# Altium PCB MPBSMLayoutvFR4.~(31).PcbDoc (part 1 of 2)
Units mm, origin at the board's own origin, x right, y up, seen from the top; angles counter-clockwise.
Board outline 131.7 x 110.39 mm, 4 copper layers (Top Layer, Power, GroundPlane, Bottom Layer), stack 2.286 mm thick; 158 components, 77 nets, 439 pads, 119 vias.
Unrouted connection lines stored in the file: 14.
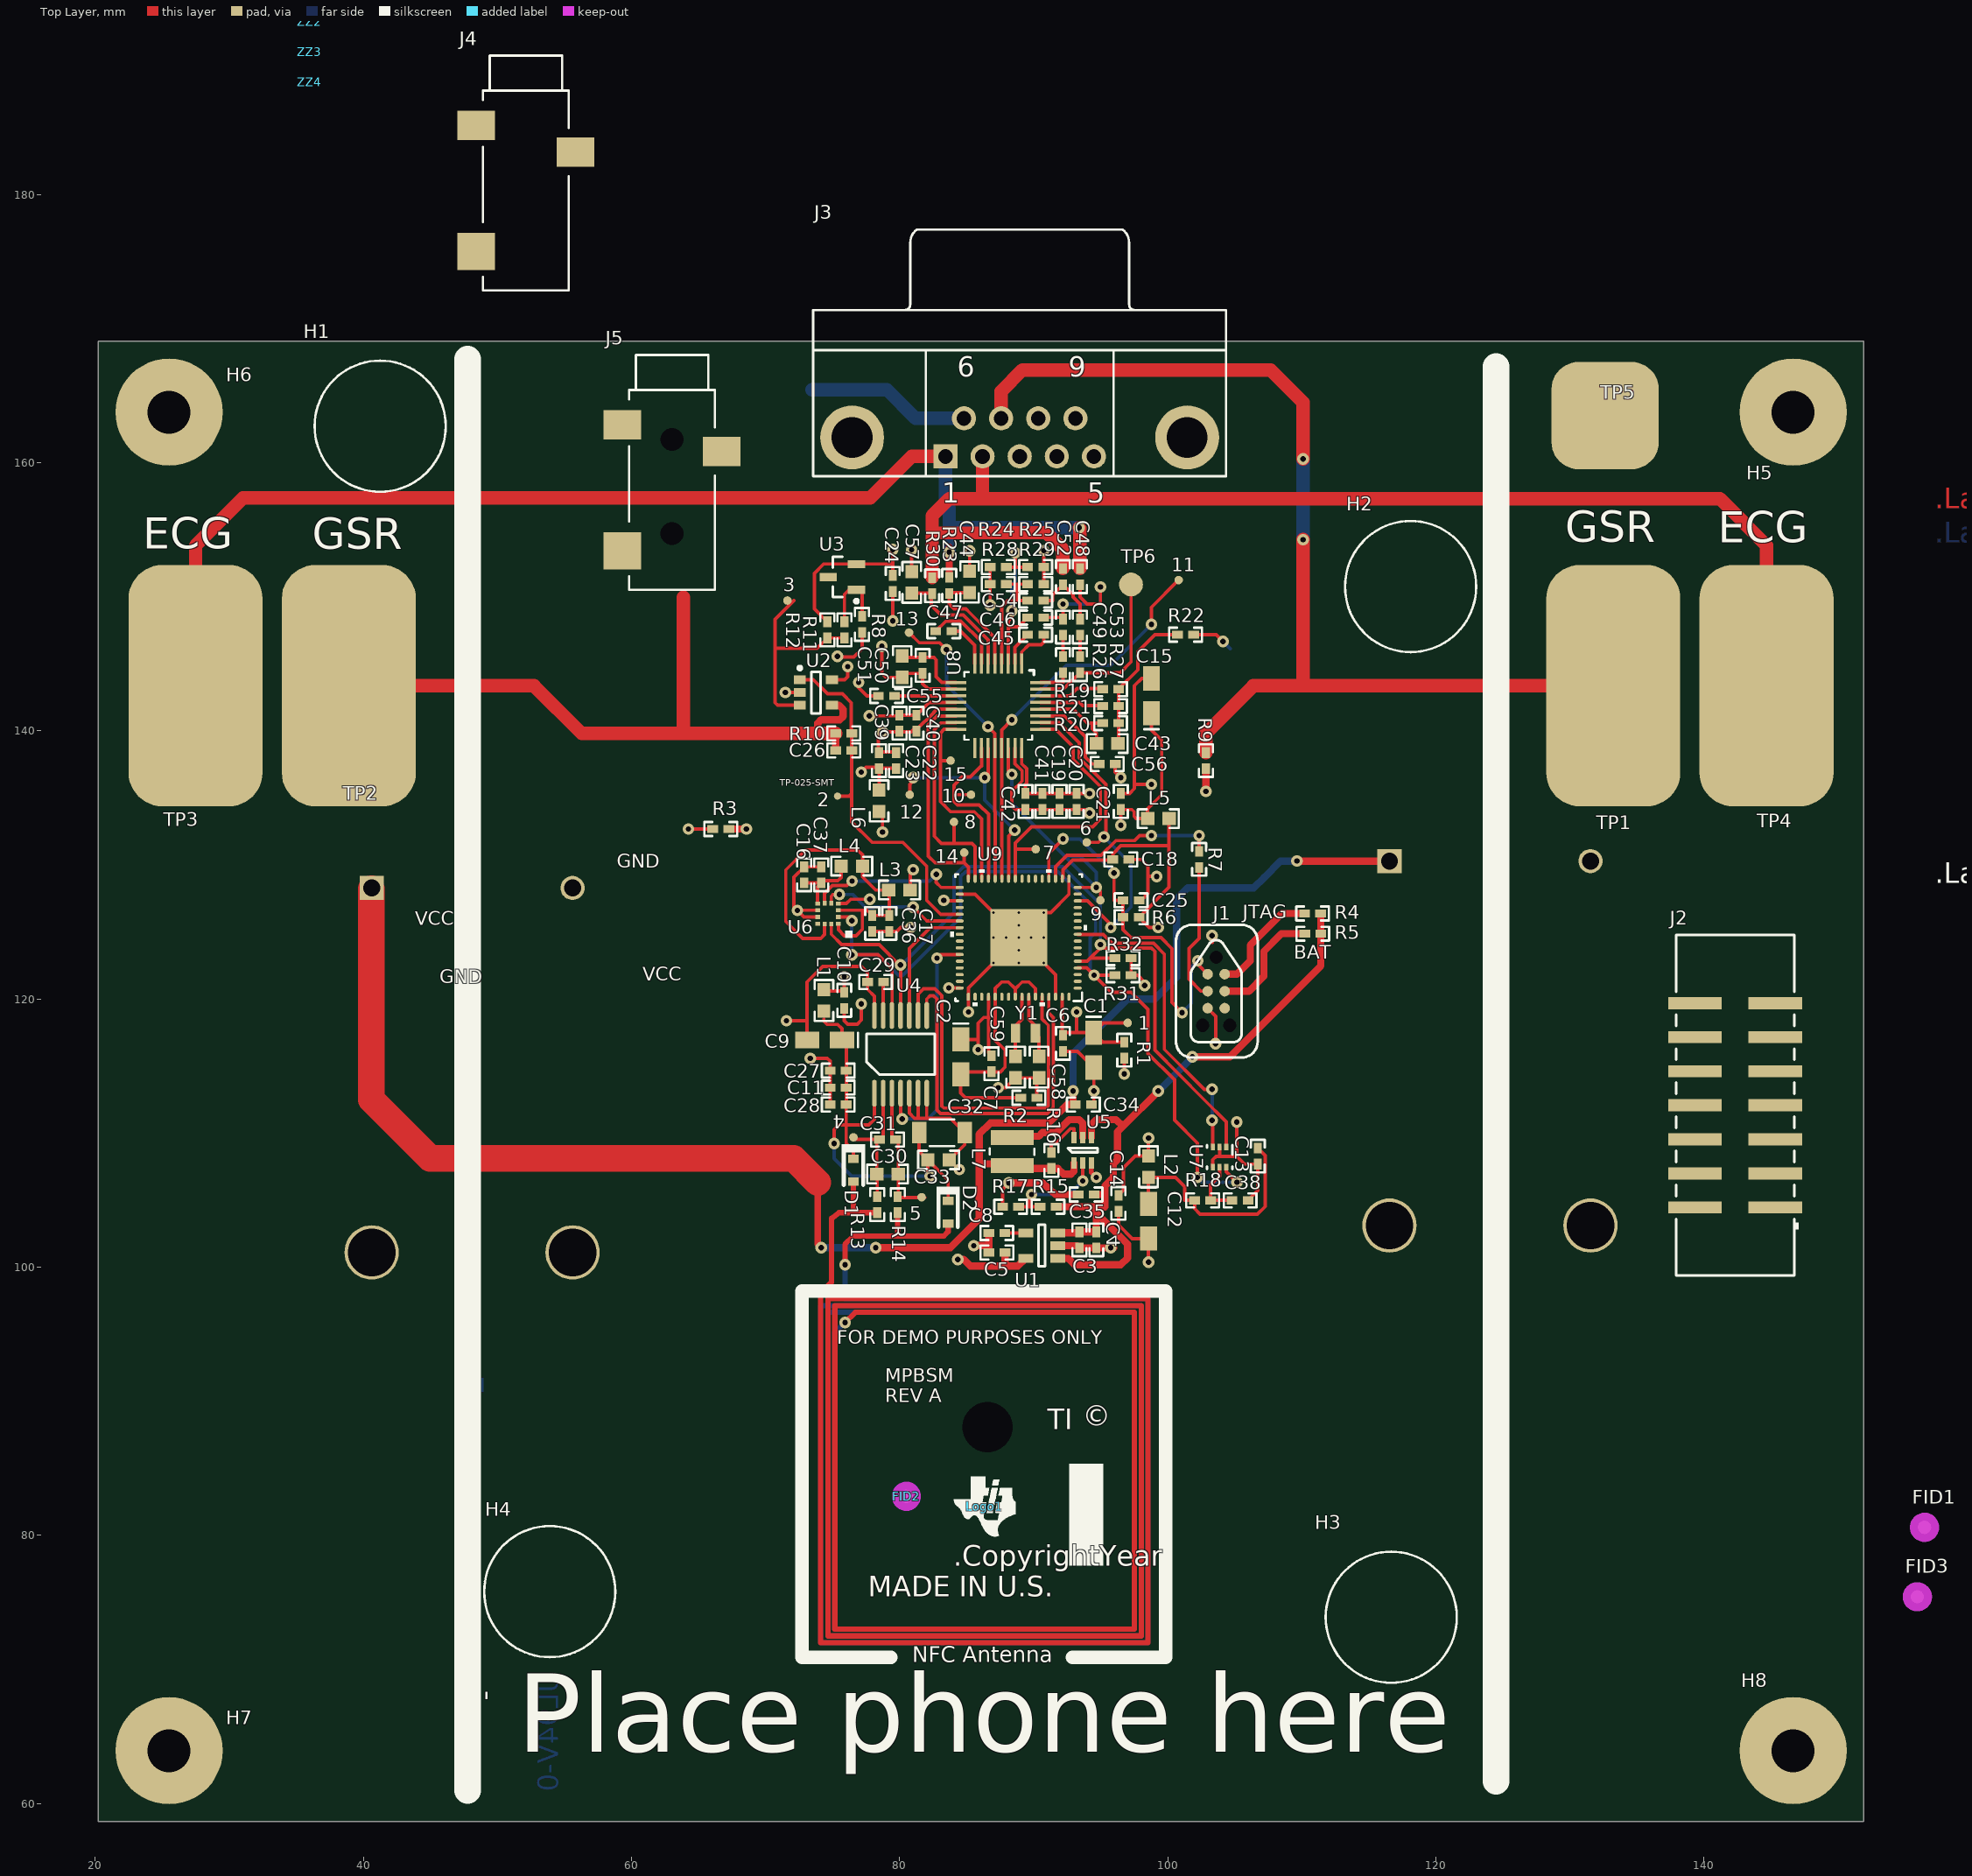
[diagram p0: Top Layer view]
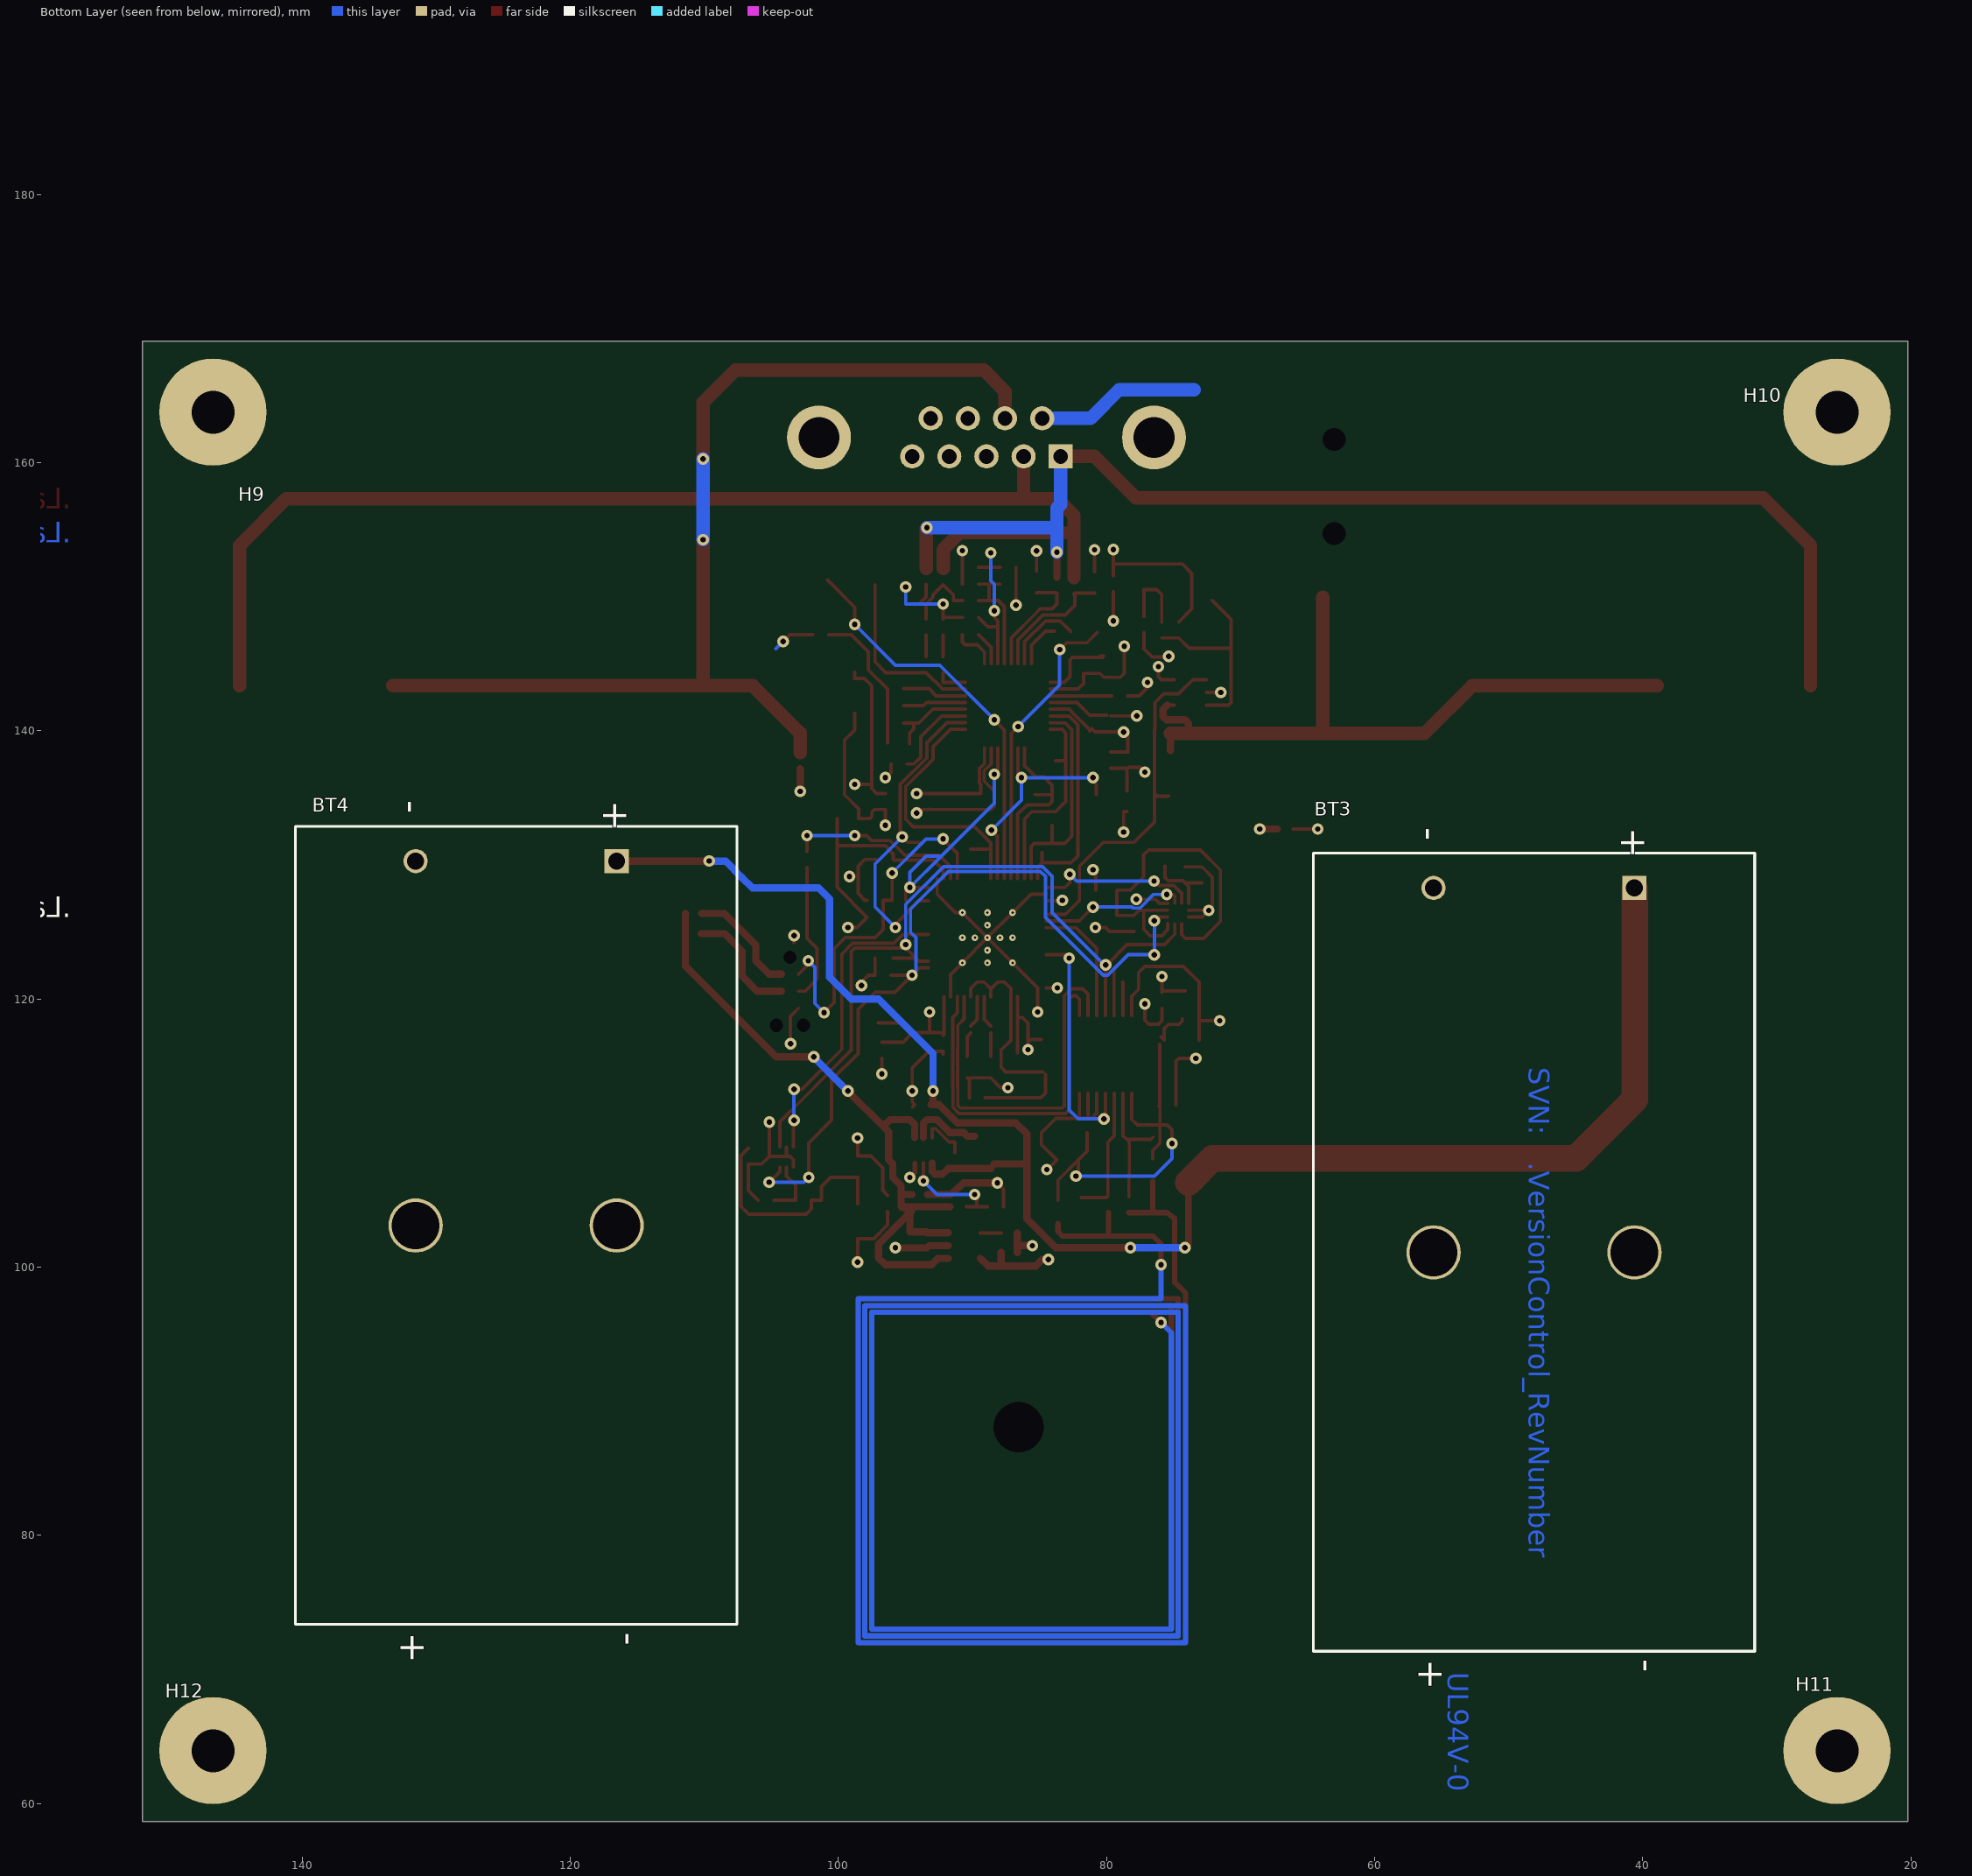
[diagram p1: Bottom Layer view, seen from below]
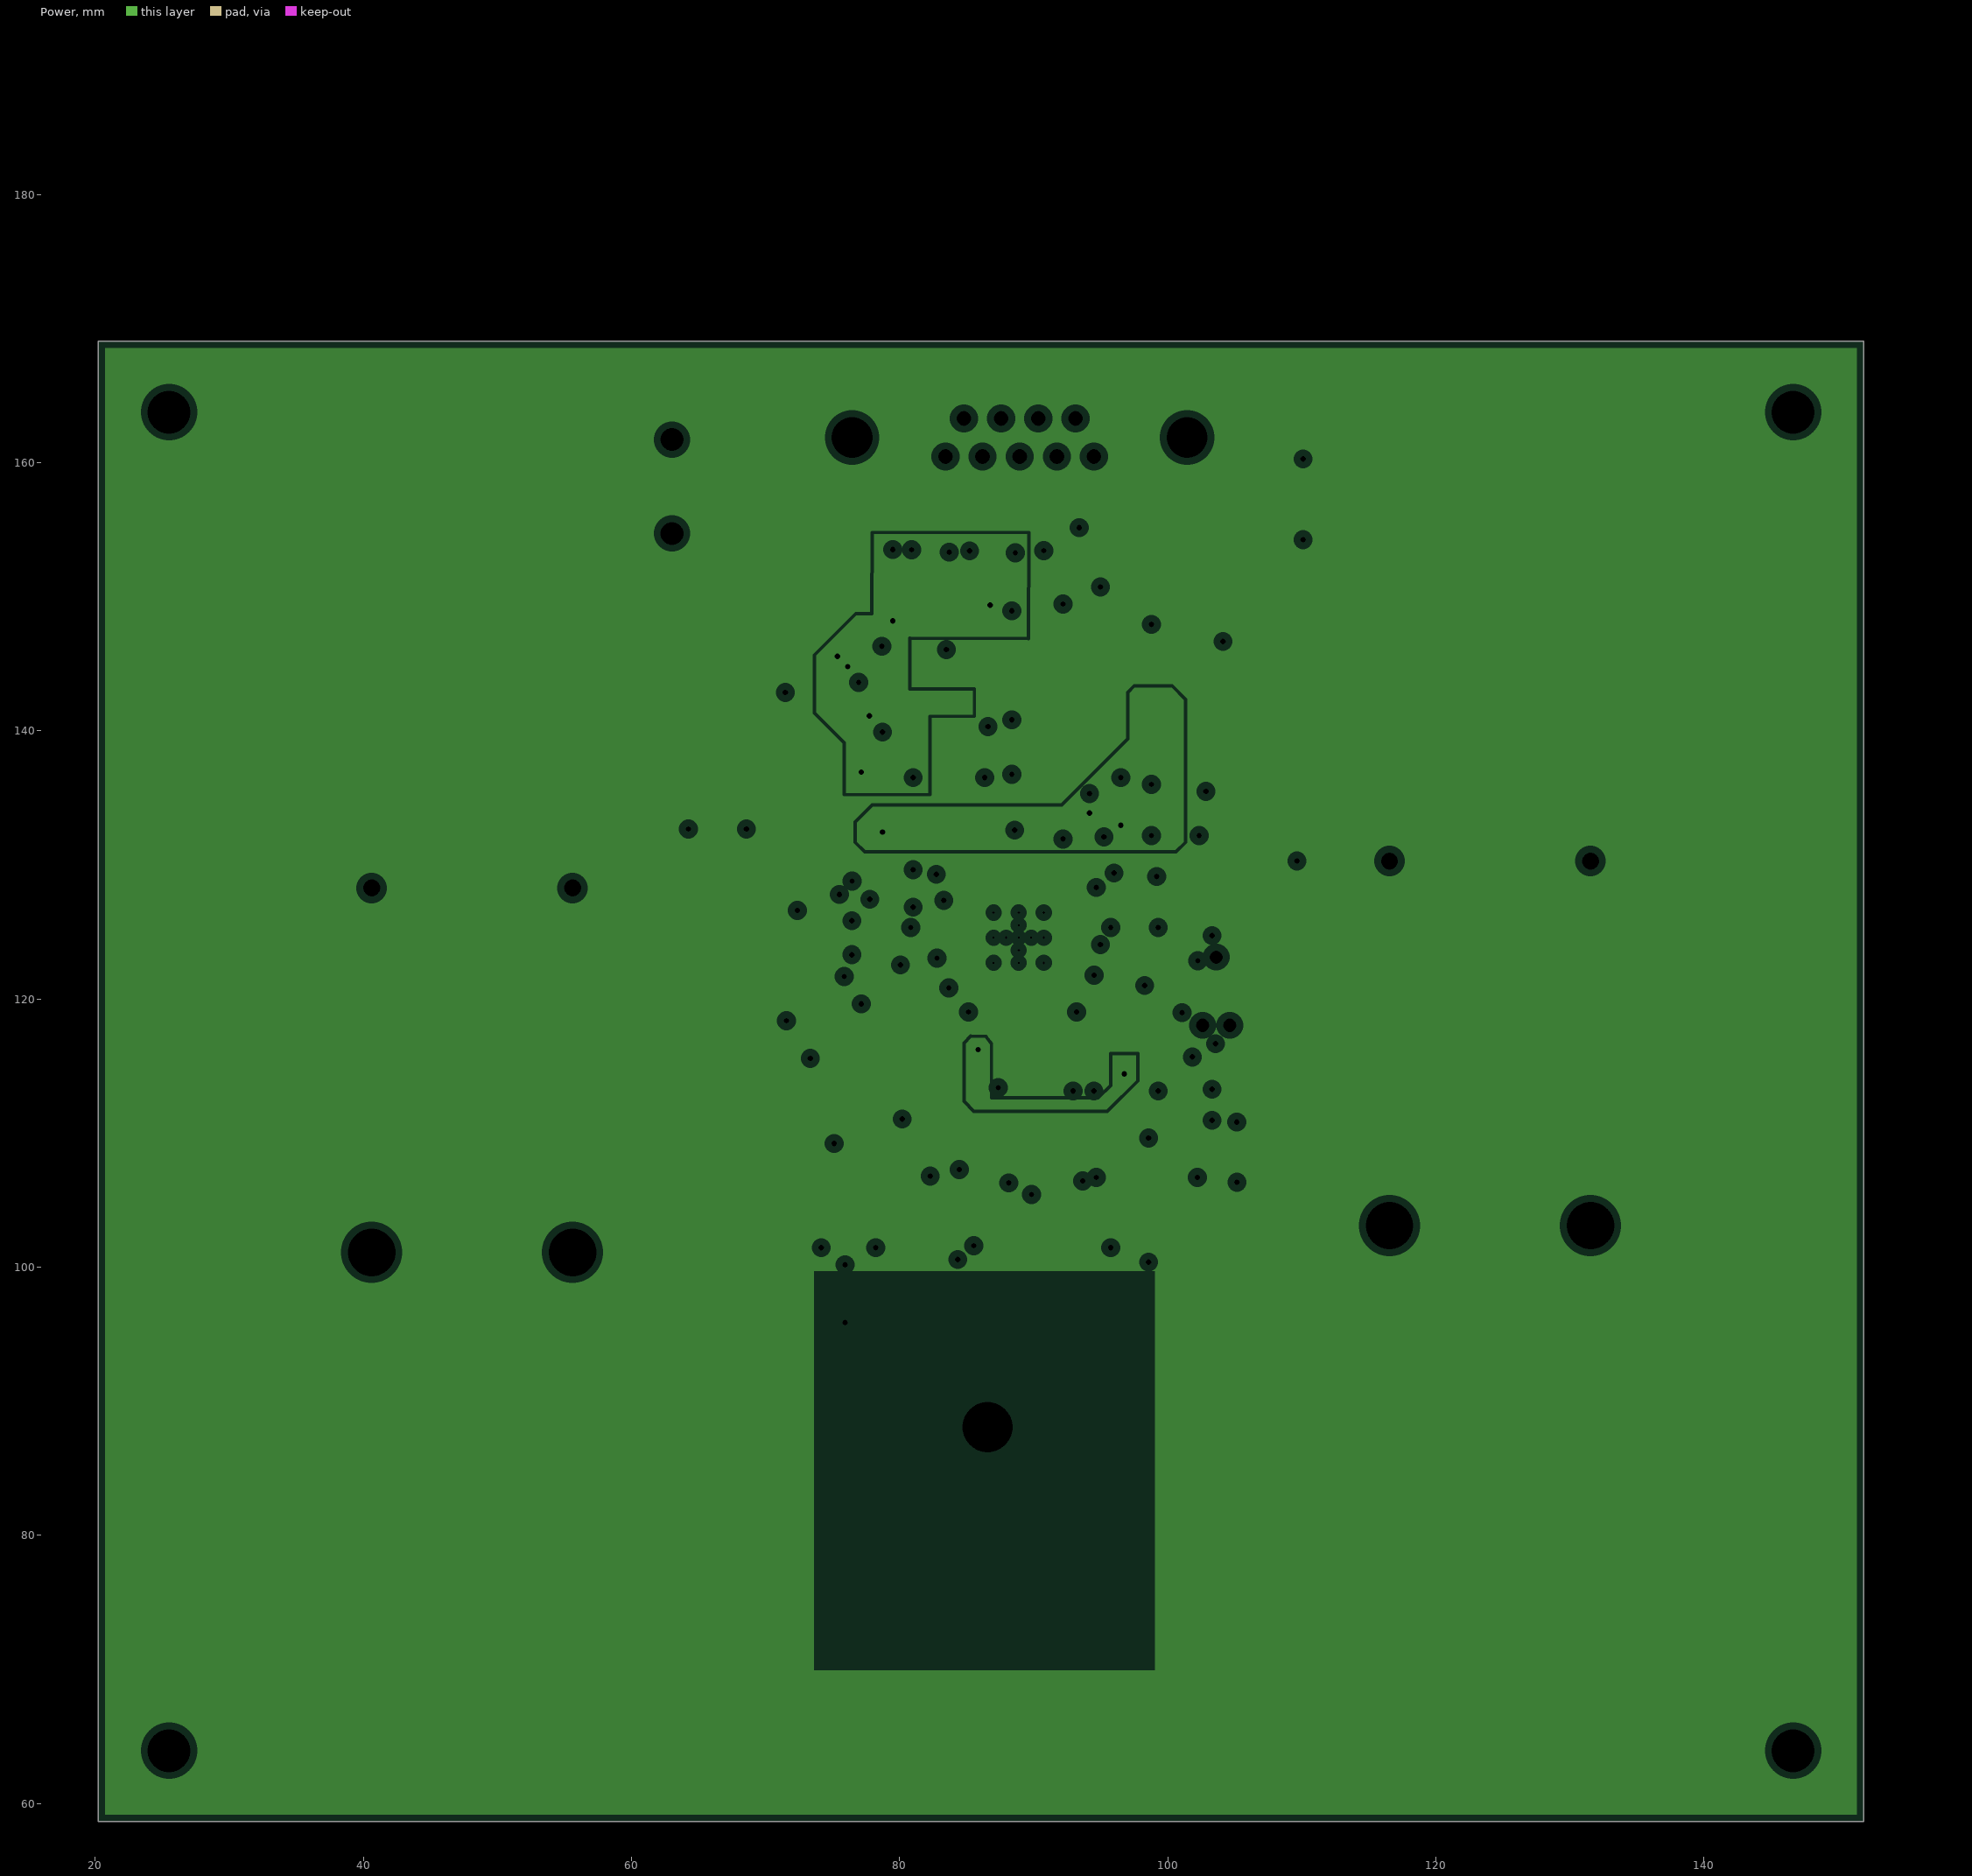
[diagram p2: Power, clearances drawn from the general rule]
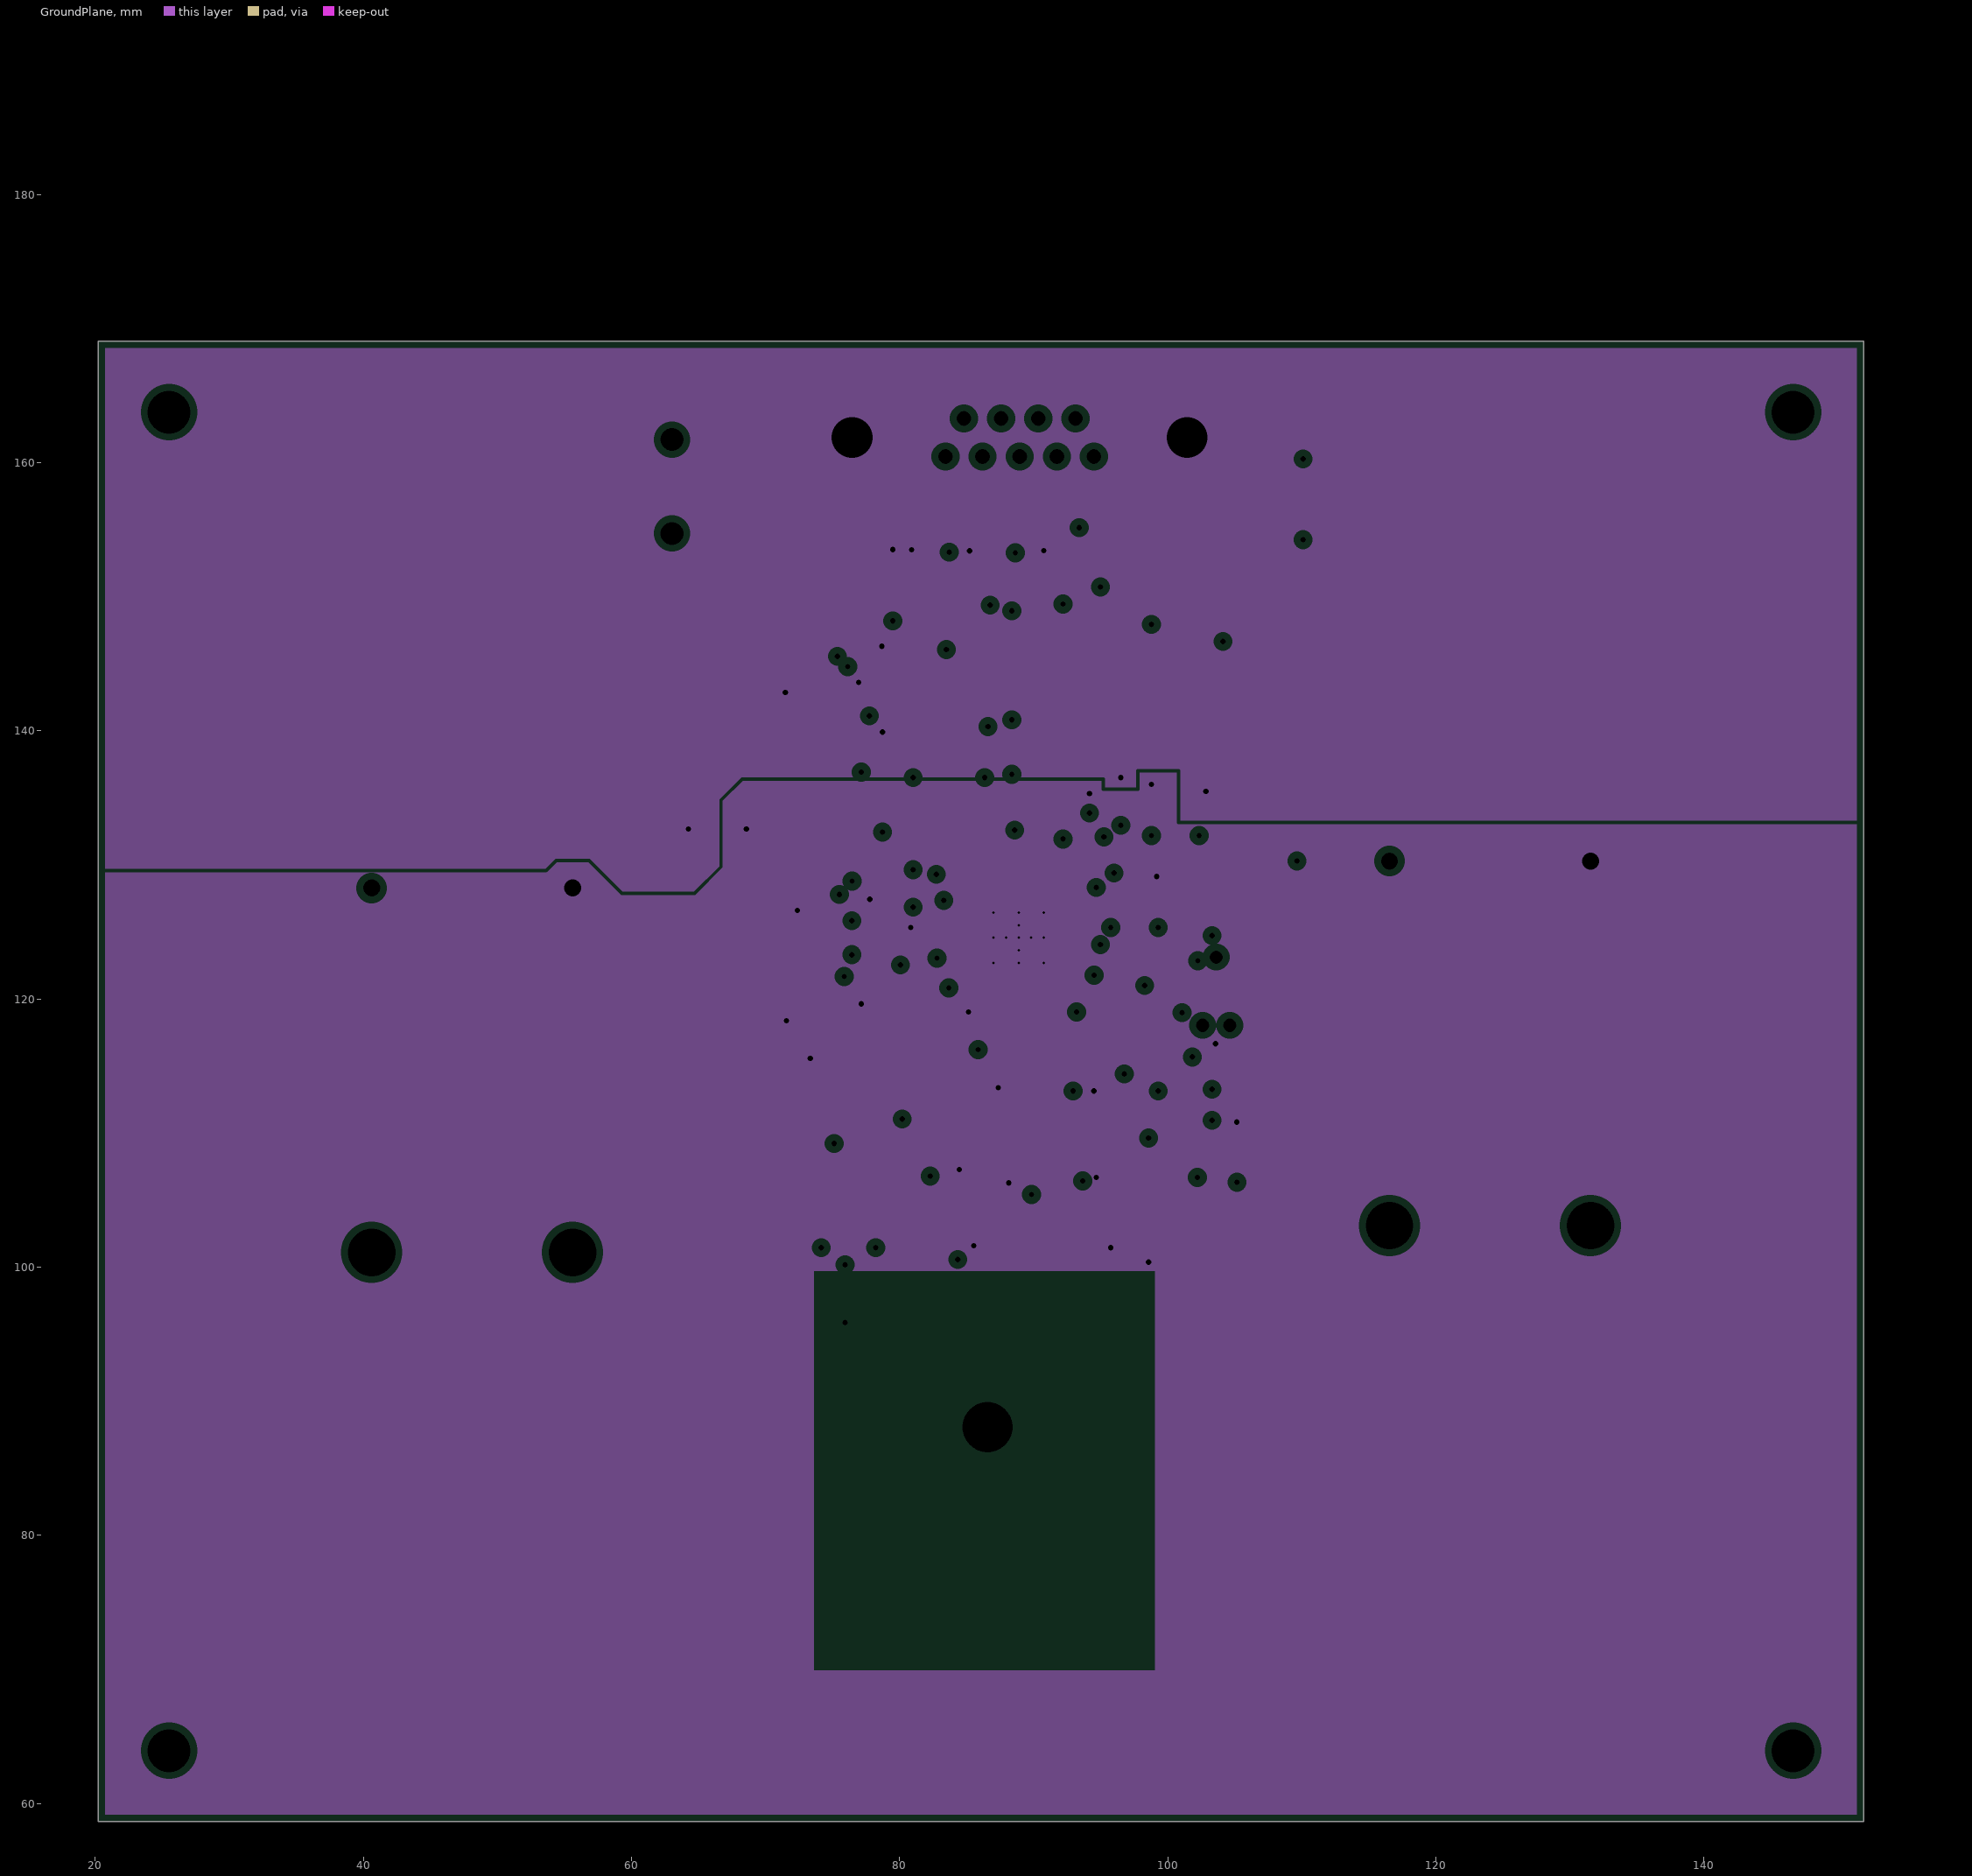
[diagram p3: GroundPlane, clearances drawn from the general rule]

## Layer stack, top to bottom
Top Solder: solder mask 0.0102, Solder Resist, Dk 3.5
Top Layer: signal copper 0.0356
Dielectric1: core 1.5037, FR-4, Dk 4.8
Power: plane copper 0.0356, net (Multiple Nets)
Dielectric2: prepreg 0.32, FR-4, Dk 4.8
GroundPlane: plane copper 0.0356, net (Multiple Nets)
Dielectric3: core 0.32, FR-4, Dk 4.8
Bottom Layer: signal copper 0.0356
Bottom Solder: solder mask 0.0102, Solder Resist, Dk 3.5

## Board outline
20.218,169.037 20.218,58.649 150.825,58.649 151.917,58.649 151.917,158.471 151.917,169.037 20.218,169.037

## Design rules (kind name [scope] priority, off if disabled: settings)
AcuteAngle [All] p1: minimum=4.50000000000000E+0001 checktracksonly=FALSE
AssemblyTestPointUsage [All] p1: valid=2
Clearance Clearance_BoardEdge_MountingHoles [OnCopper and InComponentClass('Mounting Holes') vs IsKeepOut] p1: gap=1.016
Clearance Clearance_BoardEdge_Poly [OnCopper and InPoly vs IsKeepOut] p2: gap=0.635
Clearance Clearance_BoardEdge [OnCopper and Not InComponentClass('Logo') and not InComponentClass('FiducialMark') and not InRegion(1000,500,4000,800) and Not IsKeepout vs IsKeepOut] p3: gap=1.905
Clearance Clearance_Poly [InPolygon] p4: gap=0.635
Clearance [All] p5: gap=0.1
ComponentClearance ComponentClearance_Shunt [InComponentClass('Header') vs InComponentClass('Shunt')] p1: gap=0 collisioncheckmode=3 verticalgap=0 showdistances=FALSE
ComponentClearance ComponentClearance_MountingHoles_FiducialMarks [InComponentClass('Mounting Holes') vs InComponentClass('FiducialMark')] p2: gap=1.27 collisioncheckmode=3 verticalgap=0.254 showdistances=FALSE
ComponentClearance ComponentClearance_Logo [InComponentClass('Logo')] p3: gap=1.27 collisioncheckmode=3 verticalgap=0.254 showdistances=FALSE
ComponentClearance ComponentClearance_ScrewToNut [(HasFootprint('NY PMS 440 0025 PH')) vs (HasFootprint('Keystone_1902C'))] p4: gap=0.127 collisioncheckmode=3 verticalgap=0.254 showdistances=FALSE
ComponentClearance ComponentClearance_MountingHoles [InComponentClass('Mounting Holes')] p5: gap=6.35 collisioncheckmode=3 verticalgap=2540 showdistances=FALSE
ComponentClearance ComponentClearance_SmallPassives [HasFootprint('0201*') or HasFootprint('0402*') or HasFootprint('0508') or HasFootprint('0603*') or HasFootprint('0612') or HasFootprint('0805*') or HasFootprint('0815*') or HasFootprint('0830*') or HasFootprint('1206*') or HasFootprint('1210*') or HasFootprint('1808*') or HasFootprint('1812*') or HasFootprint('1825*') or HasFootprint('2010*') or HasFootprint('2220*') or HasFootprint('2225*') or HasFootprint('2512*') or HasFootprint('2728*') or HasFootprint('3518*') vs HasFootprint('0201*') or HasFootprint('0402*') or HasFootprint('0508') or HasFootprint('0603*') or HasFootprint('0612') or HasFootprint('0805*') or HasFootprint('0815*') or HasFootprint('0830*') or HasFootprint('1206*') or HasFootprint('1210*') or HasFootprint('1808*') or HasFootprint('1812*') or HasFootprint('1825*') or HasFootprint('2010*') or HasFootprint('2220*') or HasFootprint('2225*') or HasFootprint('2512*') or HasFootprint('2728*') or HasFootprint('3518*')] p6: gap=0.508 collisioncheckmode=3 verticalgap=0.254 showdistances=FALSE
ComponentClearance ComponentClearance_THtoSMT [IsThruComponent vs IsSMTComponent] p7: gap=2.54 collisioncheckmode=3 verticalgap=0.762 showdistances=FALSE
ComponentClearance ComponentClearance_THtoTH [IsThruComponent vs IsThruComponent] p8: gap=3 collisioncheckmode=3 verticalgap=0.762 showdistances=FALSE
ComponentClearance [All] p9: gap=1.016 collisioncheckmode=3 verticalgap=0.254 showdistances=FALSE
DiffPairsRouting [All] p1: maxlimit=2.54 minlimit=0.254 mostfreqgap=0.254 toplayer_minwidth=0.381 toplayer_maxwidth=0.381 toplayer_prefwidth=0.381 bottomlayer_minwidth=0.381 bottomlayer_maxwidth=0.381 bottomlayer_prefwidth=0.381 maxuncoupledlength=25.4
FabricationTestPointUsage TestPointUsage [All] p1: valid=2 allowmultiple=FALSE
FabricationTestpoint Testpoint [All] p1: side=3 testpointundercomponent=TRUE minsize=1.016 maxsize=2.54 preferedsize=1.524 minholesize=0 maxholesize=1.016 preferedholesize=0.813 testpointgrid=0.025 allowsidetop=TRUE allowsidebottom=TRUE usegrid=TRUE gridtolerance=0
FanoutControl Fanout_LCC [IsLCC] p1: bgadir=Out bgaviamode=Centered fanoutstyle=Auto fanoutdirection=Alternating viagrid=0.025 // Fanout_LCC (Default Rule)
FanoutControl Fanout_BGA [IsBGA] p2: bgadir=Out bgaviamode=Centered fanoutstyle=Auto fanoutdirection=Alternating viagrid=0.025 // Fanout_BGA (Default Rule)
FanoutControl Fanout_Default [All] p4: bgadir=Out bgaviamode=Centered fanoutstyle=Auto fanoutdirection=Alternating viagrid=0.025 // Fanout_Default (Default Rule)
FanoutControl Fanout_Small [(CompPinCount < 5)] p5: bgadir=Out bgaviamode=Centered fanoutstyle=Auto fanoutdirection=OutThenIn viagrid=0.025 // Fanout_Small (Default Rule)
Height [All] p1: minheight=0 maxheight=55.4 prefheight=12.7
HoleSize [All] p1: absolutevalues=TRUE maxlimit=6.375 minlimit=0.1 maxpercent=80.000 minpercent=20.000
MinimumAnnularRing MinimumAnnularRing_ThermalPadVias [IsVia and InAnyComponent] p1: minimumring=0.15
MinimumAnnularRing [All] p2: minimumring=0.229
MinimumSolderMaskSliver MinimumSolderMaskSliver_Logo [InComponentClass('Logo') vs InComponentClass('Logo')] p1: minsoldermaskwidth=0.018
MinimumSolderMaskSliver [All] p2: minsoldermaskwidth=0.08
PlaneClearance [All] p1: clearance=0.508
PlaneConnect [All] p1: planeconnectstyle=Relief reliefexpansion=0.254 reliefentries=4 reliefconductorwidth=0.254 reliefairgap=0.254
PolygonConnect [All] p1: connectstyle=Relief reliefconductorwidth=0.254 reliefentries=4 polygonreliefangle="90 Angle" airgapwidth=0.254
RoutingVias ThermalPadVias [IsVia and InAnyComponent] p1: holewidth=0.2 width=0.5 viastyle="Through Hole" minholewidth=0.2 minwidth=0.5 maxholewidth=0.33 maxwidth=0.6
RoutingVias [All] p2: holewidth=0.406 width=0.864 viastyle="Through Hole" minholewidth=0.2 minwidth=0.66 maxholewidth=1.016 maxwidth=1.651
SMDToCorner [All] p1: distance=30000
SilkToSilkClearance SilkToSilkClearance_Pb-FreeLogo [(HasFootprint('Pb-Free_Overlay_Medium') OR HasFootprint('Pb-Free_Overlay_Small')) vs (HasFootprint('Pb-Free_Overlay_Medium') OR HasFootprint('Pb-Free_Overlay_Small'))] p1: silktosilkclearance=0
SilkToSilkClearance [All] p2: silktosilkclearance=0
SilkToSolderMaskClearance SilkscreenOverComponentPads [IsPad] p1: minsilkscreentomaskgap=0.127 clearancetoexposedcopper=TRUE
SolderMaskExpansion [All] p1: expansion=0.05
Width [All] p1: maxlimit=2.54 minlimit=0.152 preferedwidth=0.254 checkconnectedcopper=TRUE
14 further rules are at their usual default settings.

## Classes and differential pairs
component class "Mounting Holes": H5 H6 H7 H8
component class "Analog Connector": J3
component class Transponder: 4 5 C27 C28 C29 C30 C31 C32 C33 D1 D2 R13 R14 U4
component class Temperature: C38 R18 U7
component class "Power Filtering": 1 C1 C2 C3 C4 C5 C6 C7 C8 C9 C10 C11 C12 C13 C14 C15 C16 C17 C18 C19 C20 C21 C22 C23 C24 L1 L2 L3 L4 L5 L6 R1 R2 R3 U1
component class MSP430FR5XXX: C58 C59 R31 R32 U9 Y1
component class "JTAG SPY-BY-WIRE": C25 J1 J2 R4 R5 R6 R7
component class GSR: 2 3 C26 R8 R9 R10 R11 R12 U2 U3
component class ECG: 6 7 8 9 10 11 12 13 14 15 C39 C40 C41 C42 C43 C44 C45 C46 C47 C48 C49 C50 C51 C52 C53 C54 C55 C56 C57 R19 R20 R21 R22 R23 R24 R25 R26 R27 R28 R29 R30 TP6 U8
component class "Boost Converter": C34 C35 L7 R15 R16 R17 U5
component class BMA280: C36 C37 U6
component class Battery: BT3 BT4 U?
component class AssemblyNote: ZZ1 ZZ2 ZZ3 ZZ4
component class FiducialMark: FID1 FID2 FID3
component class Designator: FID1 FID2 FID3 H1 H2 H3 H4 H5 H6 H7 H8 H9 H10 H11 H12 Logo1 ZZ1 ZZ2 ZZ3 ZZ4
component class Logo: Logo1

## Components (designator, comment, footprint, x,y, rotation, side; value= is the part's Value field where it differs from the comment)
1 "TP-025-SMT" TP_25MIL-SMT#1 97.003,118.212 r90 top
2 "TP-025-SMT" TP_25MIL-SMT#2 75.362,135.128 r0 top
3 "TP-025-SMT" TP_25MIL-SMT#1 71.628,149.708 r0 top
4 "TP-025-SMT" TP_25MIL-SMT#1 76.551,109.676 r0 top
5 "TP-025-SMT" TP_25MIL-SMT#1 81.636,105.207 r270 top
6 "TP-025-SMT" TP_25MIL-SMT#1 93.955,131.674 r0 top
7 "TP-025-SMT" TP_25MIL-SMT#1 90.145,131.166 r0 top
8 "TP-025-SMT" TP_25MIL-SMT#1 84.049,133.198 r0 top
9 "TP-025-SMT" TP_25MIL-SMT#1 94.971,127.356 r0 top
10 "TP-025-SMT" TP_25MIL-SMT#1 85.319,135.23 r0 top
11 "TP-025-SMT" TP_25MIL-SMT#1 100.813,151.232 r0 top
12 "TP-025-SMT" TP_25MIL-SMT#1 80.747,135.23 r0 top
13 "TP-025-SMT" TP_25MIL-SMT#1 80.696,147.32 r0 top
14 "TP-025-SMT" TP_25MIL-SMT#1 84.811,130.912 r90 top
15 "TP-025-SMT" TP_25MIL-SMT#1 83.795,137.77 r0 top
BT3 "2462" Keystone_2462 48.108,114.681 r270 bottom
BT4 "2462" Keystone_2462 124.028,116.688 r270 bottom
C1 "293D106X9010A2TE3" 3216-18 94.463,116.18 r270 top
C2 "293D106X9010A2TE3" 3216-18 84.557,115.672 r270 top
C3 "C1005X5R1A104K" 0402 93.401,102.028 r270 top
C4 "C1005X5R0J105M" 0402 94.671,102.028 r270 top
C5 "C1005X5R1C225K050BC" 0402 87.254,101.092 r180 top
C6 "C1005X5R1A104K" 0402 92.177,116.688 r270 top
C7 "C1005X5R1A104K" 0402 86.843,115.164 r270 top
C8 "C1005X7R1E103K" 0402 87.249,102.54 r180 top
C9 "293D105X9016A2TE3" 3216-18 74.397,116.942 r180 top
C10 "C1005X5R1A104K" 0402 75.87,119.888 r270 top
C11 "C1005X5R1A104K" 0402 75.413,113.386 r180 top
C12 "293D106X9010A2TE3" 3216-18 98.56,103.422 r270 top
C13 "C1005X5R1A104K" 0402 106.705,108.28 r270 top
C14 "C1005X5R1A104K" 0402 96.319,104.75 r270 top
C15 "293D105X9016A2TE3" 3216-18 98.781,142.596 r90 top
C16 "CL05A106MQ5NUNC" 0402 72.873,129.247 r90 top
C17 "CL05A106MQ5NUNC" 0402 79.223,125.624 r270 top
C18 "C1005X5R1A104K" 0402 96.495,130.404 r0 top
C19 "C1005X5R1A104K" 0402 91.923,134.722 r90 top
C20 "C1005X5R1C225K050BC" 0402 93.193,134.722 r90 top
C21 "CL05A106MQ5NUNC" 0402 96.495,134.722 r90 top
C22 "CL05A106MQ5NUNC" 0402 79.731,137.77 r90 top
C23 "C1005X5R1A104K" 0402 78.461,137.77 r90 top
C24 "C1005X5R1A104K" 0402 79.477,150.978 r90 top
C25 "C1005X8R1H222K" 0402 97.257,127.356 r0 top
C26 "C1005X7R1E103K" 0402 75.829,138.532 r180 top
C27 "C1005X5R0J105M" 0402 75.413,114.656 r180 top
C28 "C1005X5R1A104K" 0402 75.413,112.116 r180 top
C29 "GRM155R60J474KE19D" 0402 78.207,121.26 r0 top
C30 "C1608C0G1H330J" 0603 79.091,106.941 r0 top
C31 "GRM1555C1H390JA01D" 0402 79.091,109.515 r0 top
C32 "C3216X5R1A107M160AC" 1206_190 83.155,110.023 r0 top
C33 "Used in BOM report" 0603 82.901,107.991 r0 top
C34 "CL05A106MQ5NUNC" 0402 93.701,112.116 r0 top
C35 "CL05A106MQ5NUNC" 0402 93.904,105.41 r180 top
C36 "C1005X5R1A104K" 0402 77.953,125.624 r270 top
C37 "C1005X5R1A104K" 0402 74.143,129.247 r90 top
C38 "C1005X7R1E103K" 0402 105.389,104.978 r0 top
C39 "C1005X5R1C105K050BC" 0402 79.985,140.564 r270 top
C40 "C1005X5R1A104K" 0402 81.255,140.564 r270 top
C41 "C1005X5R1C105K050BC" 0402 90.653,134.722 r90 top
C42 "C1005X5R1A104K" 0402 89.383,134.722 r90 top
C43 "C0603C152K5RACTU" 0603 95.479,139.04 r180 top
C44 "GRM1885C1H302JA01D" 0603 85.217,151.091 r90 top
C45 "GRM155R61A472KA01D" 0402 90.145,147.168 r0 top
C46 "C1005X8R1H222K" 0402 90.145,148.438 r0 top
C47 "GRM155R61A472KA01D" 0402 83.287,147.422 r180 top
C48 "C1005X5R1A104K" 0402 93.447,151.486 r270 top
C49 "C1005X8R1H222K" 0402 92.177,147.722 r90 top
C50 "C1005X5R1A104K" 0402 81.712,144.872 r270 top
C51 "C1608X5R0J106M" 0603 80.188,144.78 r270 top
C52 "C1005X5R1A104K" 0402 92.177,151.486 r270 top
C53 "C1005X8R1H222K" 0402 93.447,147.722 r90 top
C54 "C1005X8R1H222K" 0402 90.145,149.708 r0 top
C55 "C1005X5R1C105K050BC" 0402 79.015,142.596 r180 top
C56 "C1005X5R1C105K050BC" 0402 95.479,137.516 r0 top
C57 "GRM1885C1H302JA01D" 0603 80.895,151.063 r90 top
C58 "06035A100JAT2A" 0603 90.399,114.91 r270 top
C59 "06035A100JAT2A" 0603 88.646,114.91 r270 top
D1 "CDBU0130L" SOD-523F 76.551,107.229 r270 top
D2 "CDBU0130L" SOD-523F 83.617,104.089 r270 top
FID1 "Fiducial" Fiducial10-20 156.439,80.594 r0 top
FID2 "Fiducial" Fiducial10-20 80.493,82.906 r0 top
FID3 "Fiducial" Fiducial10-20 155.905,75.413 r0 top
H1 "SJ61A2" Bumpon_SJ61A2 41.25,162.712 r0 top
H2 "SJ61A2" Bumpon_SJ61A2 118.11,150.749 r0 top
H3 "SJ61A2" Bumpon_SJ61A2 116.662,73.889 r0 top
H4 "SJ61A2" Bumpon_SJ61A2 53.899,75.794 r0 top
H5 "NY PMS 440 0025 PH" "NY PMS 440 0025 PH" 146.634,163.754 r90 top
H6 "NY PMS 440 0025 PH" "NY PMS 440 0025 PH" 25.502,163.754 r90 top
H7 "NY PMS 440 0025 PH" "NY PMS 440 0025 PH" 25.502,63.932 r90 top
H8 "NY PMS 440 0025 PH" "NY PMS 440 0025 PH" 146.635,63.938 r90 top
H9 "1902C" Keystone_1902C 146.634,163.748 r90 bottom
H10 "1902C" Keystone_1902C 25.527,163.728 r90 bottom
H11 "1902C" Keystone_1902C 25.502,63.932 r90 bottom
H12 "1902C" Keystone_1902C 146.634,63.932 r180 bottom
J1 "TC2030-MCP-NL" TC2030-MCP-NL 103.607,120.574 r180 top
J2 "61201420621" Wurth_61201420621 142.316,112.065 r180 top
J3 "182-009-213R171" NORCOMP_182-009-213R171 88.951,171.374 r0 top
J4 "SJ-3523-SMT" CUI_SJ-3523-SMT 52.121,180.442 r270 top
J5 "SJ-3523-SMT" CUI_SJ-3523-SMT 63.017,158.115 r270 top
L1 "BLM18HG601SN1D" 0603 74.346,119.888 r270 top
L2 "BLM18HG601SN1D" 0603 98.56,107.486 r270 top
L3 "BLM18HG601SN1D" 0603 79.985,128.118 r180 top
L4 "BLM18HG601SN1D" 0603 76.429,129.896 r0 top
L5 "BLM18HG601SN1D" 0603 99.289,133.452 r180 top
L6 "BLM18HG601SN1D" 0603 78.461,134.772 r90 top
L7 "EPL3015-472MLB" EPL3015 88.392,108.61 r90 top
Logo1 "Texas Instruments" TI_Symbol_Overlay_Small 86.335,82.144 r0 top
R1 "ERJ-2GE0R00X" 0402 96.749,116.18 r270 top
R2 "ERJ-2GE0R00X" 0402 89.637,112.624 r180 top
R3 "ERJ-2GE0R00X" 0402 66.657,132.67 r180 top
R4 "ERJ-2GE0R00X" 0402 110.795,126.365 r0 top
R5 "ERJ-2GE0R00X" 0402 110.814,124.861 r0 top
R6 "CRCW040247K0JNED" 0402 97.257,126.086 r0 top
R7 "ERJ-2GE0R00X" 0402 102.337,130.404 r90 top
R8 "CRCW040221K5FKED" 0402 77.191,147.93 r270 top
R9 "CRCW040210K0FKED" 0402 102.845,137.77 r90 top
R10 "ERJ-2RKF1004X" 0402 75.829,139.802 r0 top
R11 "CRCW040211K8FKED" 0402 75.875,147.517 r90 top
R12 "CRCW04028K06FKED" 0402 74.605,147.517 r270 top
R13 "ERJ-2GE0R00X" 0402 78.329,104.655 r270 top
R14 "ERJ-2GE0R00X" 0402 79.853,104.655 r270 top
R15 "ERJ-2RKF1004X" 0402 91.069,104.496 r0 top
R16 "ERJ-2GE0R00X" 0402 91.313,107.95 r90 top
R17 "ERJ-2RKF2003X" 0402 88.275,104.496 r0 top
R18 "CRCW04024K99FKED" 0402 102.595,104.978 r180 top
R19 "ERJ-2GE0R00X" 0402 95.733,143.104 r0 top
R20 "ERJ-2RKF1004X" 0402 95.733,140.564 r0 top
R21 "ERJ-2RKF1003X" 0402 95.733,141.834 r0 top
R22 "ERJ-2RKF1003X" 0402 101.321,147.168 r0 top
R23 "CRCW040251K1FKED" 0402 83.693,150.837 r270 top
R24 "CRCW040210M0FKED" 0402 87.351,152.202 r180 top
R25 "CRCW040210M0FKED" 0402 90.145,152.202 r180 top
R26 "CRCW040240K2FKED" 0402 92.177,144.928 r270 top
R27 "CRCW040240K2FKED" 0402 93.447,144.928 r270 top
R28 "CRCW040210M0FKED" 0402 87.351,150.932 r180 top
R29 "CRCW040210M0FKED" 0402 90.145,150.932 r180 top
R30 "CRCW040251K1FKED" 0402 82.419,150.809 r270 top
R31 "CRCW04023K30JNED" 0402 96.657,121.768 r180 top
R32 "CRCW04023K30JNED" 0402 96.657,123.038 r180 top
TP1 "TESTPOINT" TP_SM_1MM#1 133.223,143.358 r0 top
TP2 "TESTPOINT" TP_SM_1MM#2 38.913,143.358 r90 top
TP3 "TESTPOINT" TP_SM_1MM#2 27.483,143.358 r90 top
TP4 "TESTPOINT" TP_SM_1MM#2 144.653,143.358 r90 top
TP5 "TESTPOINT" TP_SM_1MM#3 132.613,163.5 r90 top
TP6 "Pogo Pad" PogoPad 97.257,150.901 r0 top locked
U1 "TPS73030DBVR" DBV0005A_N 90.602,101.6 r180 top
U2 "LMP2231AMFE" MF05A_L 73.751,142.85 r0 top
U3 "LM4041AIM3-1.2" MF03A_N 75.717,151.46 r180 top
U4 "RF430CL331HCPW" PW0014A_M 80.067,115.864 r90 top
U5 "TPS61220DCK" DCK0006A_N 93.65,108.712 r90 top
U6 "BMA280" LGA-12P 74.651,126.361 r90 top
U7 "TMP112AIDRL" DRL0006A 103.859,108.206 r270 top
U8 "ADS1292RIPBS" PBS0032A_N 87.351,141.853 r270 top
U9 "MSP430FR5889IRGCR" RGC0064B 88.875,124.562 r180 top
Y1 "FC-12M 32.7680KA-A3" Epson_FC-12M 89.383,117.45 r0 top
ZZ1 "This Assembly Note is for PCB labels only" AssemblyNoteLabel 35.992,195.631 r0 top
ZZ2 "These assemblies are ESD sensitive, ESD precautions shall be observed." AssemblyNote 35.992,192.865 r0 top
ZZ3 "These assemblies must be clean and free from flux and all contaminants. Use of no clean flux is not acceptable." AssemblyNote 35.992,190.616 r0 top
ZZ4 "These assemblies must comply with workmanship standards IPC-A-610 Class 2, unless otherwise specified." AssemblyNote 35.992,188.366 r0 top

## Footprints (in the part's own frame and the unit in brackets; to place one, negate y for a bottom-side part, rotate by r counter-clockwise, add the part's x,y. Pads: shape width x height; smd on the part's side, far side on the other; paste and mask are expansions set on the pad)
0402 [mm] "0402 from SM-752 data"
  rect 0.8x0.6 smd: 1(-0.6,0) 2(0.6,0)
  silkscreen extent -1.22,-0.52 1.22,0.52, body extent -0.55,-0.3 0.55,0.3, height 0.6
0603 [mm] "0603 from SM-752 data"
  rect 1x0.95 smd: 1(-0.8,0) 2(0.8,0)
  silkscreen extent -1.52,-0.69 1.52,0.69, body extent -0.87,-0.47 0.87,0.47, height 0.85
1206_190 [mm] "1206_190"
  rect 1.1x1.6 smd: 1(-1.7,0) 2(1.7,0)
  silkscreen extent -0.9,-1 0.9,1, body extent -1.75,-0.95 1.75,0.95, height 1.9
3216-18 [mm] "Medium density IPC, based on Kemet T495 dimensions"
  rect 1.8x1.25 smd: 1(-1.3,0) 2(1.3,0)
  silkscreen extent -2.49,-0.54 -2.49,0.54, body extent -1.7,-0.9 1.7,0.9, height 1.8
AssemblyNote [mm] "Assembly Note"
AssemblyNoteLabel [mm] "Assembly Note for PCB Labels"
Bumpon_SJ61A2 [mil] "3M Hemispherical Bumpon transparent"
  round 1 on Mech3: 0(0,0)
  silkscreen extent -192,-192 192,192, body extent -191,-192 193,192, height 250
CUI_SJ-3523-SMT [mm] "CUI recommended land pattern Rev C CUI_SJ-3523-SMT_Datasheet.pdf"
  rect 2.2x2.8 smd: 1(-4.7,-3.7) 3(-2.7,3.7)
  rect 2.8x2.8 smd: 2(4.7,-3.7)
  round 0 hole 1.7 unplated: 4(-3.6,0) 5(3.4,0)
  silkscreen extent -9.9,-3.2 7.6,3.2, body extent -9.6,-4.5 7.4,4.5, height 5.12
DBV0005A_N [mm] "SOT23, 5-Leads, Body 2.9x1.6mm, Pitch 0.95mm, Lead Span 2.8mm, IPC Medium Density"
  rect 1.1x0.65 smd: 1(-1.2,0.95) 2(-1.2,0) 3(-1.2,-0.95) 4(1.2,-0.95) 5(1.2,0.95)
  silkscreen extent -0.25,-1.55 0.25,1.55, body extent -1.42,-1.46 1.42,1.46, height 1.08
DCK0006A_N [mm] "SOT23, 6-Leads, Body 2x1.3mm, Pitch 0.65mm, Lead Span 2.1mm, IPC Medium Density"
  rect 0.85x0.4 smd: 1(-0.95,0.65) 2(-0.95,0) 3(-0.95,-0.65) 4(0.95,-0.65) 5(0.95,0) 6(0.95,0.65)
  silkscreen extent -0.15,-1.1 0.15,1.1, body extent -1.14,-1 1.14,1, height 0.94
DRL0006A [mm] "SOTFL, 6-Flat Leads, Body 1.2x1.6x0.6mm, Pitch 0.5mm, TI recommended"
  rect 0.5x0.3 smd: 1(-0.75,0.5) 2(-0.75,0) 3(-0.75,-0.5) 4(0.75,-0.5) 5(0.75,0) 6(0.75,0.5)
  silkscreen extent -0.9,-0.95 0.9,0.95, body extent -0.85,-0.85 0.85,0.85, height 0.62
EPL3015 [mm] "COILCRAFT"
  rect 1.12x3.2 smd: 1(-1.04,0) 2(1.04,0)
  silkscreen extent -0.22,-1.65 0.23,1.68, body extent -1.6,-1.6 1.6,1.6, height 1.55
Epson_FC-12M [mm] "Epson"
  rect 0.7x1.4 smd: 1(-0.75,0) 2(0.75,0)
  body extent -1.05,-0.63 1.05,0.63, height 0.6
Fiducial10-20 [mm]
  round 1 smd mask+0.5: 1(0,0)
  Top Layer keep-out circle w1.178: c0,0 r0.5
Keystone_1902C [mil] "Hex Standoff, 4-40 threaded, nylon"
  round 1 on Mech4: 0(0,0)
  body extent -145,-126 146,126, height 501
Keystone_2462 [mm] "2x AA Battery Holder, Through-hole mount"
  rect 1.8x1.8 hole 1.27: 1(-13.59,7.495)
  round 1.8 hole 1.27: 2(-13.59,-7.495)
  round 4.05 hole 3.55: 3(13.59,-7.495) 4(13.59,7.495)
  silkscreen extent -16.18,-16.46 43.33,16.46, body extent -16.31,-16.46 43.4,16.46, height 16
LGA-12P [mm]
  rect 0.3x0.35 smd mask+0.05: 1(-0.75,-0.775) 2(-0.25,-0.775) 3(0.25,-0.775) 4(0.75,-0.775) 7(0.75,0.775) 8(0.25,0.775) 9(-0.25,0.775) 10(-0.75,0.775)
  rect 0.35x0.3 smd mask+0.05: 5(0.775,-0.25) 6(0.775,0.25) 11(-0.775,0.25) 12(-0.775,-0.25)
  silkscreen extent -1.8,-1.8 -1.29,-1.3
MF03A_N [mm] "SOT23, 3-Leads, Body 2.9x1.3mm, Pitch 0.95mm, Lead Span 2.4mm, IPC Medium Density"
  rect 1.3x0.6 smd: 1(-1.05,0.95) 2(-1.05,-0.95) 3(1.05,0)
  silkscreen extent -1.18,-1.5 0.7,1.92, body extent -0.7,-1.5 0.7,1.5, height 1.12
MF05A_L [mm] "SOT23, 5-Leads, Body 2.9x1.6mm, Pitch 0.95mm, Lead Span 2.8mm, IPC High Density"
  rect 0.9x0.65 smd: 1(-1.2,0.95) 2(-1.2,0) 3(-1.2,-0.95) 4(1.2,-0.95) 5(1.2,0.95)
  silkscreen extent -1.32,-1.55 0.35,1.95, body extent -0.9,-1.55 0.9,1.55, height 1.19
NORCOMP_182-009-213R171 [mm] "Connector; D Subminiature 9 Position; Right Angle"
  rect 1.8x1.8 hole 1.092: 1(-5.54,-10.92)
  round 1.8 hole 1.092: 2(-2.77,-10.92) 3(0,-10.92) 4(2.77,-10.92) 5(5.54,-10.92) 6(-4.155,-8.08) 7(-1.385,-8.08) 8(1.385,-8.08) 9(4.155,-8.08)
  round 4.76 hole 3.05: 10(-12.495,-9.5) 11(12.495,-9.5)
  silkscreen extent -15.4,-12.4 15.4,6, body extent -15.41,-12.98 15.41,6.1, height 12.55
"NY PMS 440 0025 PH" [mm] "4-40 nylon screw and mounting hole"
  round 8 hole 3.2: 1(0,0)
  body extent -3.3,-3.3 3.3,3.3, height 2.69
PBS0032A_N [mil]
  rect 60x9 smd: 1(-124,68.9) 2(-124,49.21) 3(-124,29.53) 4(-124,9.84) 5(-124,-9.84) 6(-124,-29.53) 7(-124,-49.21) 8(-124,-68.9) 17(124,-68.9) 18(124,-49.21) 19(124,-29.53) 20(124,-9.84) 21(124,9.84) 22(124,29.53) 23(124,49.21) 24(124,68.9)
  rect 9x60 smd: 9(-68.9,-124) 10(-49.21,-124) 11(-29.53,-124) 12(-9.84,-124) 13(9.84,-124) 14(29.53,-124) 15(49.21,-124) 16(68.9,-124) 25(68.9,124) 26(49.21,124) 27(29.53,124) 28(9.84,124) 29(-9.84,124) 30(-29.53,124) 31(-49.21,124) 32(-68.9,124)
  silkscreen extent -104,-100 100,104, body extent -140,-140 140,140, height 48
PogoPad [mil] "No Solder Paste"
  round 70 smd paste-35: 1(0,0)
PW0014A_M [mm] "TSOP, 14-Leads, Body 5x4.4mm, Pitch 0.65mm, IPC Low Density"
  oval 2x0.35 smd: 1(-2.9,1.95) 2(-2.9,1.3) 3(-2.9,0.65) 4(-2.9,0) 5(-2.9,-0.65) 6(-2.9,-1.3) 7(-2.9,-1.95) 8(2.9,-1.95) 9(2.9,-1.3) 10(2.9,-0.65) 11(2.9,0) 12(2.9,0.65) 13(2.9,1.3) 14(2.9,1.95)
  silkscreen extent -1.5,-2.55 1.53,2.55, body extent -3.21,-2.5 3.21,2.5, height 0.98
RGC0064B [mm]
  oval 0.6x0.24 smd mask+0.07: 1(-4.4,3.75) 2(-4.4,3.25) 3(-4.4,2.75) 4(-4.4,2.25) 5(-4.4,1.75) 6(-4.4,1.25) 7(-4.4,0.75) 8(-4.4,0.25) 9(-4.4,-0.25) 10(-4.4,-0.75) 11(-4.4,-1.25) 12(-4.4,-1.75) 13(-4.4,-2.25) 14(-4.4,-2.75) 15(-4.4,-3.25) 16(-4.4,-3.75) 33(4.4,-3.75) 34(4.4,-3.25) 35(4.4,-2.75) 36(4.4,-2.25) 37(4.4,-1.75) 38(4.4,-1.25) 39(4.4,-0.75) 40(4.4,-0.25) 41(4.4,0.25) 42(4.4,0.75) 43(4.4,1.25) 44(4.4,1.75) 45(4.4,2.25) 46(4.4,2.75) 47(4.4,3.25) 48(4.4,3.75)
  oval 0.24x0.6 smd mask+0.07: 17(-3.751,-4.4) 18(-3.251,-4.4) 19(-2.751,-4.4) 20(-2.251,-4.4) 21(-1.75,-4.4) 22(-1.25,-4.4) 23(-0.75,-4.4) 24(-0.25,-4.4) 25(0.25,-4.4) 26(0.75,-4.4) 27(1.25,-4.4) 28(1.75,-4.4) 29(2.251,-4.4) 30(2.751,-4.4) 31(3.251,-4.4) 32(3.751,-4.4) 49(3.751,4.4) 50(3.251,4.4) 51(2.751,4.4) 52(2.251,4.4) 53(1.75,4.4) 54(1.25,4.4) 55(0.75,4.4) 56(0.25,4.4) 57(-0.25,4.4) 58(-0.75,4.4) 59(-1.25,4.4) 60(-1.75,4.4) 61(-2.251,4.4) 62(-2.751,4.4) 63(-3.251,4.4) 64(-3.751,4.4)
  rect 4.25x4.25 smd paste-2.112: 65(0,0)
  silkscreen extent -5.1,-5.1 5.1,5.1, body extent -4.57,-4.57 4.57,4.57, height 1.01
SOD-523F [mm] "COMCHIP"
  rect 0.6x0.8 smd paste-0.05: 1(-0.85,0) 2(0.85,0)
  silkscreen extent -1.92,-0.87 1.1,0.88, body extent -0.9,-0.5 0.9,0.5, height 0.85
TC2030-MCP-NL [mil] "TAG-CONNECT"
  round 31 smd paste-16: 1(-25,-50) 2(25,-50) 3(-25,0) 4(25,0) 5(-25,50) 6(25,50)
  round 25 hole 39 unplated: MH1(0,-100) MH2(-40,100) MH3(40,100)
  silkscreen extent -122,-195 118,195
TI_Symbol_Overlay_Small [mm]
  silkscreen extent -2.3,-2.23 2.3,2.24
TP_25MIL-SMT#1 [mm]
  round 0.635 smd mask-0.064: 1(0,0)
TP_25MIL-SMT#2 [mm]
  round 0.535 smd mask-0.064: 1(0,0)
TP_SM_1MM#1 [mm] "1mm Test Point, SMT"
  rrect50% 10x18 smd paste-0.5: 1(0,0)
TP_SM_1MM#2 [mm] "1mm Test Point, SMT"
  rrect50% 18x10 smd paste-0.5: 1(0,0)
TP_SM_1MM#3 [mm] "1mm Test Point, SMT"
  rrect50% 8x8 smd paste-0.5: 1(0,0)
Wurth_61201420621 [mm] "Header, 2.54mm, 7x2, SMT"
  rect 4x0.9 smd: 1(-3,7.62) 2(3,7.62) 3(-3,5.08) 4(3,5.08) 5(-3,2.54) 6(3,2.54) 7(-3,0) 8(3,0) 9(-3,-2.54) 10(3,-2.54) 11(-3,-5.08) 12(3,-5.08) 13(-3,-7.62) 14(3,-7.62)
  silkscreen extent -4.75,-12.7 4.4,12.7, body extent -4.75,-12.7 4.75,12.7, height 10.43

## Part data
1 2 3 4 5 6 7 8 9 10 11 12 13 14 15: "Test Point, O.025\""
BT3 BT4: "2x AA Battery Holder, Through-hole mount"
C1 C2 C12: "CAP, TA, 10 µF, 10 V, +/- 10%, 3.4 ohm, SMD"
C3 C6 C7 C10 C11 C13 C14 C18 C19 C23 C24 C28 C36 C37 C40 C42 C48 C50 C52: "CAP, CERM, 0.1 µF, 10 V, +/- 10%, X5R, 0402"
C4 C27: "CAP, CERM, 1 µF, 6.3 V, +/- 20%, X5R, 0402"
C5 C20: "CAP, CERM, 2.2 µF, 16 V, +/- 10%, X5R, 0402"
C8 C26 C38: "CAP, CERM, 0.01 µF, 25 V, +/- 10%, X7R, 0402"
C9 C15: "CAP, TA, 1 µF, 16 V, +/- 10%, 9.3 ohm, SMD"
C16 C17 C21 C22 C34 C35: "CAP, CERM, 10 µF, 6.3 V, +/- 20%, X5R, 0402"
C25 C46 C49 C53 C54: "CAP, CERM, 2200 pF, 50 V, +/- 10%, X8R, 0402"
C29: "CAP, CERM, 0.47 µF, 6.3 V, +/- 10%, X5R, 0402"
C30: "CAP, CERM, 33 pF, 50 V, +/- 5%, C0G/NP0, 0603"
C31: "CAP, CERM, 39pF, 50V, +/-5%, C0G/NP0, 0402"
C32: "CAP, CERM, 100 µF, 10 V, +/- 20%, X5R, 1206_190"
C33: library part Capacitor, "CAP, CERM, xxxF, xxV, [TempCo], xx%, [PackageReference]"
C39 C41 C55 C56: "CAP, CERM, 1 µF, 16 V, +/- 10%, X5R, 0402"
C43: "CAP, CERM, 1500 pF, 50 V, +/- 10%, X7R, 0603"
C44 C57: "CAP, CERM, 3000 pF, 50 V, +/- 5%, C0G/NP0, 0603"
C45 C47: "CAP, CERM, 4700 pF, 10 V, +/- 10%, X5R, 0402"
C51: "CAP, CERM, 10 µF, 6.3 V, +/- 20%, X5R, 0603"
C58 C59: "CAP, CERM, 10 pF, 50 V, +/- 5%, C0G/NP0, 0603"
D1 D2: "Diode, Schottky, 35V, 0.1A, SOD-523F"
FID1 FID2 FID3: "Fiducial mark.  There is nothing to buy or mount."
H1 H2 H3 H4: "Bumpon, Hemisphere, 0.375 X 0.235, Black"
H5 H6 H7 H8: "Machine Screw, Round, #4-40 x 1/4, Nylon, Philips panhead"
H9 H10 H11 H12: "Standoff, Hex, 0.5\"L #4-40 Nylon"
J1: "Footprint for TC2030-MCP-NL"
J2: "Header(Shrouded), 2.54mm, 7x2, Gold, Black, SMT"
J3: "CONN DB9 FEMALE R/A SOLDER TH"
J4 J5: "Audio Jack, 3.5mm, Stereo, R/A, SMT"
L1 L2 L3 L4 L5 L6: "Ferrite Bead, 600 ohm @ 100MHz, 0.2A, 0603"
L7: "Inductor, Shielded, Ferrite, 4.7uH, 1.2A, 0.14 ohm, SMD"
Logo1: library part TI_Logo, "Texas Instrument Corporate Signature"
R1 R2 R3 R4 R5 R7 R13 R14 R16 R19: "RES, 0, 5%, 0.063 W, 0402"
R6: "RES, 47 k, 5%, 0.063 W, 0402"
R8: "RES, 21.5 k, 1%, 0.063 W, 0402"
R9: "RES, 10.0 k, 1%, 0.063 W, 0402"
R10 R15 R20: "RES, 1.00 M, 1%, 0.1 W, 0402"
R11: "RES, 11.8 k, 1%, 0.063 W, 0402"
R12: "RES, 8.06 k, 1%, 0.063 W, 0402"
R17: "RES, 200 k, 1%, 0.1 W, 0402"
R18: "RES, 4.99 k, 1%, 0.063 W, 0402"
R21 R22: "RES, 100 k, 1%, 0.1 W, 0402"
R23 R30: "RES, 51.1 k, 1%, 0.063 W, 0402"
R24 R25 R28 R29: "RES, 10.0 M, 1%, 0.063 W, 0402"
R26 R27: "RES, 40.2 k, 1%, 0.063 W, 0402"
R31 R32: "RES, 3.3 k, 5%, 0.063 W, 0402"
TP1 TP2 TP3 TP4 TP5: library part TP_SM_1MM, "1mm Test Point, SMT"
TP6: library part PogoPad, "Pad for Pogo Pin Connector"
U1: "Single Output High PSRR LDO, 200 mA, Fixed 3 V Output, 2.7 to 5.5 V Input, 5-pin SOT-23 (DBV), -40 to 85 degC, Green (RoHS & no Sb/Br)"
U2: "Single Micropower Precision Op Amp"
U3: "Precision Micropower Shunt Voltage Reference, 3-pin SOT-23"
U4: library part RF430CL331H, "The Texas Instruments Dynamic NFC Interface Transponder RF430CL331H is an NFC Tag Type 4 device  that combines a wireless NFC interface and a wired SPI or I2C interface to connect the device to a host."
U5: "LOW INPUT VOLTAGE STEP-UP CONVERTER IN 6 PIN SC-70 PACKAGE, DCK0006A"
U6: library part BMA250, "14 bit, digital, triaxial acceleration sensor with intelligent on-chip motion triggered interrupt controller"
U7: "High-Accuracy, Low-Power, Digital Temperature Sensor With SMBus(TM)/Two-Wire Serial Interface, DRL0006A"
U8: "Low-Power, 2-Channel, 24-Bit Analog Front-End for Biopotential Measurement, PBS0032A"
U9: "Mixed-Signal Microcontrollers, RGC0064B"
Y1: "Crystal, 32.768kHz, 12.5pF, SMD"
ZZ1: library part AssemblyNoteLabel
ZZ2 ZZ3 ZZ4: library part AssemblyNote

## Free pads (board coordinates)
  round 0 hole 3.762 unplated: 0(86.563,88.062)

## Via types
v1: diameter 0.864, hole 0.406, Top Layer to Bottom Layer, 106 vias
v2: diameter 0.5, hole 0.2, Top Layer to Bottom Layer, 13 vias

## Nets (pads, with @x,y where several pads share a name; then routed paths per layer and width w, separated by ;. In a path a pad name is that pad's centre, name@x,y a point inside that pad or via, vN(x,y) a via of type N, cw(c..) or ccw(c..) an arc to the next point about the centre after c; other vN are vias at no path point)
3V: C3.1 C4.1 C35.1 R4.2 R5.2 R15.2 U1.1 U1.3 U5.4 | length 53.6
  Top Layer w0.254: U1.3@91.802,102.55 U1.3@91.879,102.628 ; 93.04,100.178 93.142,100.178 ; C3.1@93.323,102.55 C3.1@93.401,102.628 ; 95.317,106.02 95.317,106.061
  Top Layer w0.54: R15.2@91.669,104.496 95.317,104.496 ; U1.1@91.802,100.65 92.568,100.65 93.04,100.178 ; U1.3@91.802,102.55 C3.1@93.323,102.55 ; 93.142,100.178 96.495,100.178 97.003,100.686 97.003,101.702 94.555,104.15 95.317,104.496 ; C3.1@93.401,102.628 C4.1@94.671,102.628 94.671,104.034 ; U5.4@94.3,109.662 94.3,110.632 94.666,110.998 96.139,110.998 96.647,110.49 ; C35.1@94.504,105.41 95.317,105.41 ; 95.317,106.02 95.317,105.41 ; 95.317,106.061 95.936,106.68 95.936,107.696 96.241,108.001 96.241,110.084 96.647,110.49 ; v1(99.289,113.132) 96.647,110.49 ; v1(101.829,115.672) 104.623,115.672 111.414,122.463 R5.2@111.414,124.816 ; R4.2@111.395,126.365 111.414,126.346 R5.2@111.414,124.861 ; 95.317,104.496 95.317,105.41
  Bottom Layer w0.54: v1(99.289,113.132) v1(101.829,115.672)
ADS1292_DRDY: 9.1 U8.22 U9.16 | length 19.6
  Top Layer w0.254: U8.22@88.101,138.704 88.101,137.039 88.367,136.773 v1(88.367,136.754) ; U9.16@93.275,128.312 v1(94.657,128.312) 94.971,127.998 9.1@94.971,127.356
  Bottom Layer w0.254: v1(88.367,136.754) 88.367,134.602 92.311,130.658 ; 92.311,130.658 93.447,130.658 94.657,129.448 v1(94.657,128.312) 92.311,130.658
ADS1292_ELA: C52.1 J3.2 J4.3 R30.1 TP4.1 | length 94.2
  Top Layer w1: R30.1@82.419,151.409 82.419,154.733 ; J3.2@86.181,160.454 86.182,157.302 ; C52.1@92.177,152.086 92.177,153.518 90.907,154.788 82.419,154.733 ; TP4.1@144.653,143.358 144.653,153.822 141.173,157.302 87.351,157.302 83.693,157.302 82.419,156.028 82.419,154.733
ADS1292_ERA: C48.1 J3.1 J4.2 R23.1 TP3.1 | length 91.2
  Top Layer w0.54: R23.1@83.693,151.437 v1@83.693,153.67
  Top Layer w1: TP3.1@27.483,143.358 27.483,153.822 31.013,157.353 77.8,157.353 80.901,160.454 J3.1@83.411,160.454 ; v1(93.396,155.143) 93.447,155.092 C48.1@93.447,152.086
  Bottom Layer w1: J3.1@83.411,160.454 83.411,156.873 83.693,156.591 v1(83.693,153.314) ; 83.896,155.143 v1(93.396,155.143)
ADS1292_GPIO1: 6.1 U8.26 U9.14 | length 24.5
  Top Layer w0.254: U8.26@90.5,140.603 91.883,140.603 93.398,139.089 93.398,137.976 95.382,135.992 ; U9.14@93.275,127.312 93.999,127.312 95.721,125.59 v1@95.721,125.336 ; 6.1@93.955,131.674 94.825,131.674 v1(95.231,132.08) 95.387,132.236 95.387,135.992
  Bottom Layer w0.254: v1(95.231,132.08) 97.257,130.055 97.257,126.848 v1(95.733,125.324)
ADS1292_GPIO2: 7.1 U8.25 U9.25 | length 20.5
  Top Layer w0.254: U9.25@88.625,128.962 88.625,129.729 ; 88.624,129.73 88.624,131.626 89.84,132.842 94.412,132.842 94.971,133.401 94.971,135.839 92.944,137.866 92.944,138.8 91.641,140.103 U8.25@90.5,140.103 ; 88.624,131.166 7.1@90.145,131.166
ADS1292_IN1N: C46.1 R24.1 R25.2 U8.3 | length 12.8
  Top Layer w0.254: R24.1@87.951,152.202 88.621,152.202 ; U8.3@88.101,145.003 88.101,148.184 88.367,148.45 v1(88.367,148.946) ; 88.176,147.753 88.86,147.753 C46.1@89.545,148.438 ; v1(88.621,153.264) 88.621,152.202 ; R25.2@89.545,152.202 88.621,152.202
  Bottom Layer w0.254: v1(88.367,148.946) 88.367,150.932 88.621,151.186 v1(88.621,153.264)
ADS1292_IN1P: C54.1 R28.1 R29.2 U8.4 | length 9.1
  Top Layer w0.254: U8.4@87.601,145.003 87.601,149.246 88.062,149.708 C54.1@89.545,149.708 ; R28.1@87.951,150.932 88.748,150.932 ; 88.748,149.835 88.748,150.932 ; R29.2@89.545,150.932 88.748,150.932
ADS1292_IN2N: C44.1 R23.2 U8.5 | length 8.7
  Top Layer w0.254: C44.1@85.217,150.291 83.747,150.291 R23.2@83.693,150.237 83.693,149.447 84.049,149.092 84.933,149.092 85.217,148.807 87.101,146.924 U8.5@87.101,145.003
ADS1292_IN2P: C57.1 R30.2 U8.6 | length 9.5
  Top Layer w0.254: C57.1@80.895,150.263 82.365,150.263 R30.2@82.419,150.209 ; R30.2@82.365,150.209 82.365,149.359 83.087,148.638 84.745,148.638 86.601,146.782 U8.6@86.601,145.003
ADS1292_MAIN_CLKSEL: 14.1 U8.14 U9.32 | length 17.1
  Top Layer w0.254: U8.14@84.201,141.103 82.791,141.103 82.125,140.437 82.125,130.658 82.633,130.15 84.811,130.15 ; 14.1@84.811,130.912 84.811,130.15 ; U9.32@85.124,128.962 85.124,129.837 84.811,130.15
ADS1292_RESET: 8.1 U8.15 U9.31 | length 16.9
  Top Layer w0.254: 8.1@84.049,132.944 84.049,131.597 ; U8.15@84.201,140.603 84.181,140.583 83.087,140.583 82.579,140.075 82.579,132.128 83.109,131.597 84.049,131.597 ; U9.31@85.624,128.962 85.624,131.368 85.395,131.597 84.049,131.597
ADS1292_RESP_MODP/IN3N: R26.2 U8.32 | length 2.4
  Top Layer w0.254: U8.32@90.5,143.603 92.168,143.603 92.177,143.612 R26.2@92.177,144.328
ADS1292_RESP_MODP/IN3P: R27.2 TP6.1 U8.31 | length 13.4
  Top Layer w0.254: U8.31@90.5,143.103 92.222,143.103 R27.2@93.447,144.328 96.449,144.328 97.257,145.136 TP6.1@97.257,150.901
ADS1292_RLD: J3.4 J4.1 R22.2 TP5.1 | length 3.2
  Top Layer w0.254: R22.2@101.921,147.168 103.607,147.168 v1(104.115,146.66)
  Bottom Layer w0.254: v1(104.115,146.66) 104.648,146.126
ADS1292_SPI_CS: 10.1 U8.18 U9.29 | length 14.1
  Top Layer w0.254: 84.141,135.23 10.1@85.319,135.23 ; 86.055,137.328 85.268,136.541 84.649,136.541 84.049,135.941 84.049,134.722 84.303,134.468 85.927,134.468 86.624,133.771 U9.29@86.624,128.962 ; 86.101,137.374 U8.18@86.101,138.704
ADS1292_SPI_DIN: 12.1 U8.19 U9.26 | length 17.3
  Top Layer w0.254: 12.1@80.747,135.23 80.747,135.992 81.001,136.246 v1(81.001,136.5) ; v1@86.601,136.766 U8.19@86.601,138.704 ; U9.26@88.124,128.962 88.124,132.143 v1(88.57,132.588)
  Bottom Layer w0.254: v1(81.001,136.5) v1(86.335,136.5) 86.335,134.823 v1(88.57,132.588)
ADS1292_SPI_DOUT: 11.1 U8.21 U9.27 | length 29.7
  Top Layer w0.254: U9.27@87.624,128.962 87.624,134.074 87.601,134.098 U8.21@87.601,138.704 87.601,140.052 v1(88.367,140.818) ; v1(98.781,147.93) 98.781,149.2 11.1@100.813,151.232
  Bottom Layer w0.254: v1(88.367,140.818) 92.431,144.882 95.733,144.882 v1(98.781,147.93)
ADS1292_SPI_SCLK: 13.1 U8.20 U9.28 | length 21.9
  Top Layer w0.254: 13.1@80.696,147.32 81.458,146.558 82.982,146.558 v1(83.49,146.05) ; v1(86.589,140.31) 87.097,139.802 87.097,133.96 87.124,133.932 U9.28@87.124,128.962
  Bottom Layer w0.254: v1(83.49,146.05) 83.49,143.408 v1(86.589,140.31)
ADS1292_START: 15.1 U8.16 U9.30 | length 15.2
  Top Layer w0.254: 83.033,137.77 15.1@83.795,137.77 ; U8.16@84.201,140.103 83.315,140.103 83.033,139.821 83.033,138.204 83.033,134.722 83.795,133.96 85.573,133.96 86.124,133.408 U9.30@86.124,128.962
ADS1292_VCAP1: C55.1 U8.11 | length 4.6
  Top Layer w0.254: C55.1@79.622,142.603 U8.11@84.201,142.603
ADS1292_VCAP2: C56.1 U8.27 | length 6.8
  Top Layer w0.254: U8.27@90.5,141.103 92.299,141.103 93.852,139.55 93.852,138.022 94.358,137.516 C56.1@94.879,137.516
ADS1292_VREFP: C50.1 C51.1 U8.9 | length 5.9
  Top Layer w0.254: C51.1@80.483,145.58 C51.1@80.188,145.58 80.296,145.472 C50.1@81.712,145.472 82.544,145.472 82.728,145.288 82.728,144.018 83.143,143.603 U8.9@84.201,143.603
ADS_AVCC: C22.1 C23.1 C24.1 C39.1 C40.1 L6.2 R8.2 R24.2 R28.2 U2.5 U8.12 | length 21.4
  Top Layer w0.254: U2.5@74.951,143.8 75.905,143.8 76.124,144.018 v1(76.124,144.78) ; v1(75.362,145.542) 75.411,145.493 76.583,145.493 77.191,146.101 R8.2@77.191,147.33 ; v1(77.14,136.906) 77.503,137.27 78.357,137.27 C23.1@78.415,137.212 ; v1(77.733,141.106) C39.1@79.685,141.106 ; L6.2@78.461,135.522 78.461,137.166 C23.1@78.415,137.212 ; v1(79.477,148.184) C24.1@79.477,150.378 ; C22.1@79.685,137.212 C23.1@78.415,137.212 ; C39.1@79.985,141.164 C40.1@81.255,141.164 82.194,142.103 U8.12@84.201,142.103 ; v1(86.751,149.362) R28.2@86.751,150.932 R24.2@86.751,152.202
ADS_AVSS: C22.2 C23.2 C24.2 C39.2 C40.2 C44.2 C50.2 C51.2 C55.2 C56.2 C57.2 J3.10 J3.11 R3.2 R9.1 R12.1 R25.1 R29.1 U2.2 U3.2 U8.10 U8.13 | length 43.8
  Top Layer w0.254: v1(64.241,132.67) R3.2@66.057,132.67 ; v1(71.465,142.85) U2.2@72.551,142.85 ; R12.1@74.605,148.117 73.635,149.088 73.635,151.74 74.331,152.436 77.583,152.436 79.411,152.436 ; v1@76.683,143.612 v1(76.937,143.612) 76.937,143.205 77.546,142.596 C55.2@78.415,142.596 ; v1(78.664,146.304) 78.664,144.272 78.956,143.98 C51.2@80.188,143.98 80.48,144.272 C50.2@81.712,144.272 81.712,143.51 82.118,143.104 82.727,143.104 U8.10@84.201,143.103 ; C24.2@79.477,151.578 v1(79.477,153.518) ; C22.2@79.685,138.412 78.415,138.412 78.415,139.906 79.685,139.906 80.851,139.906 C40.2@81.082,140.137 ; C57.2@80.895,151.863 v1(80.895,153.496) ; C40.2@81.255,139.964 81.255,140.068 82.548,141.362 ; 82.548,141.373 82.779,141.603 U8.13@84.201,141.603 ; C44.2@85.217,151.891 v1(85.217,153.416) ; R29.1@90.745,150.932 R25.1@90.745,152.202 v1(90.745,153.426) ; C56.2@96.079,137.516 96.079,136.916 v1(96.495,136.5)
  Top Layer w0.54: v1(102.845,135.484) R9.1@102.845,137.17
  other v1: 78.715,139.906
ADS_DVCC: C15.1 C19.1 C20.1 C21.1 C41.1 C42.1 L5.2 L6.1 U8.23 | length 25
  Top Layer w0.254: L6.1@78.461,133.972 78.715,133.972 v1(78.715,132.436) ; 88.367,135.484 88.367,134.376 88.621,134.122 C42.1@89.383,134.122 C41.1@90.653,134.122 C19.1@91.923,134.122 C20.1@93.193,134.122 ; 88.383,135.5 89.129,136.246 89.129,137.008 88.601,137.536 U8.23@88.601,138.704 ; C20.1@93.221,134.15 C20.1@93.193,134.122 ; v1(94.158,133.858) 94.158,133.896 93.932,134.122 C20.1@93.193,134.122 ; v1(96.495,132.944) C21.1@96.495,134.122 97.323,134.122 97.485,133.96 97.485,133.604 97.638,133.452 L5.2@98.489,133.452 98.489,134.176 99.543,135.23 99.543,139.294 98.781,140.056 C15.1@98.781,141.296
ANTENNA: D1.2 D2.2 R13.2 R14.2 | length 600.2
  Top Layer w0.4: v1(75.921,95.86) 76.683,96.622 97.511,96.622 97.511,73 75.159,73 75.159,97.13 98.019,97.13 98.019,72.492 74.651,72.492 74.651,97.638 98.527,97.638 98.527,71.984 74.092,71.984 74.092,98.044 74.905,98.857 74.905,103.631 75.46,104.055 76.551,104.055 ; v1(75.921,100.178) 75.921,101.702 76.53,102.311 83.287,102.311 83.617,102.641 D2.2@83.617,103.239 ; D1.2@76.551,106.379 76.551,104.055 ; R13.2@78.329,104.055 76.551,104.055 ; 79.853,102.311 R14.2@79.853,104.055
  Bottom Layer w0.4: 74.092,97.079 74.092,71.984 98.527,71.984 98.527,97.638 75.921,97.638 v1(75.921,100.178) ; 74.143,97.13 98.019,97.13 98.019,72.492 74.651,72.492 74.651,96.622 97.511,96.622 97.511,73 75.159,73 75.159,95.098 v1(75.921,95.86)
BMA_AVCC: C16.1 C37.1 L4.1 U6.7 | length 5.4
  Top Layer w0.254: C16.1@72.873,128.647 C37.1@74.143,128.647 ; U6.7@73.876,127.111 73.876,128.38 C37.1@74.143,128.647 ; L4.1@75.629,129.896 75.629,129.045 75.389,128.805 74.301,128.805 C37.1@74.143,128.647
BMA_DVCC: C17.1 C36.1 L3.2 L4.2 U6.1 U6.3 U6.11 | length 28.6
  Top Layer w0.254: U6.11@74.401,125.586 74.401,124.794 74.117,124.511 72.771,124.511 71.501,125.781 71.501,129.616 73,131.115 76.86,131.115 77.229,130.747 L4.2@77.229,129.896 77.229,129.096 78.207,128.118 L3.2@79.185,128.118 79.223,128.08 C17.1@79.223,126.224 C36.1@77.953,126.224 77.566,126.611 U6.3@75.426,126.611 ; U6.1@75.426,125.611 75.426,125.158 75.87,124.714 76.733,124.714 77.216,125.197 77.216,126.585
BMA_INT1: U6.5 U9.38 | length 11
  Top Layer w0.254: U6.5@74.901,127.136 74.901,127.657 75.036,127.792 v1(75.511,127.792) ; v1(81.001,126.848) 82.017,125.832 ; 82.037,125.812 U9.38@84.475,125.812
  Bottom Layer w0.254: v1(75.511,127.792) 76.48,127.792 77.498,126.774 78.044,126.774 78.118,126.848 v1(81.001,126.848)
BMA_INT2: U6.6 U9.33 | length 12.2
  Top Layer w0.254: U6.6@74.401,127.136 74.401,127.88 74.972,128.451 76.048,128.451 76.374,128.778 v1(76.454,128.778) ; v1(82.728,129.286) 82.728,128.676 83.093,128.312 U9.33@84.475,128.312
  Bottom Layer w0.254: v1(76.454,128.778) 82.22,128.778 v1(82.728,129.286)
BOOST_INPUT: BT3.1 BT4.1 C34.1 L7.1 R16.1 U5.1 | length 128.2
  Top Layer w0.254: L7.1@88.393,107.681 L7.1@88.402,107.672 ; v1(92.939,113.132) v1@93.101,112.97
  Top Layer w0.5: 73.889,106.299 73.889,101.702 v1(74.143,101.448)
  Top Layer w0.54: v1(78.207,101.448) 83.795,101.448 85.928,103.581 85.928,109.906 86.766,110.744 91.11,110.744 92.481,112.116 C34.1@93.101,112.116 ; 85.928,107.696 L7.1@88.393,107.681 ; L7.1@88.612,107.35 R16.1@91.313,107.35 91.799,107.35 92.215,106.934 92.786,106.934 93,107.148 U5.1@93,107.762 ; C34.1@92.939,112.278 v1(92.939,113.132) ; v1(109.627,130.278) BT4.1@116.533,130.278
  Top Layer w2: BT3.1@40.589,128.22 40.589,112.497 44.983,108.102 72.085,108.102 73.889,106.299
  Bottom Layer w0.54: v1(74.143,101.448) v1(78.207,101.448) ; v1(92.939,113.132) 92.939,115.926 97.003,119.99 99.035,119.99 100.651,121.606 100.651,127.448 101.49,128.287 106.418,128.287 107.189,129.058 108.408,130.278 v1(109.627,130.278)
